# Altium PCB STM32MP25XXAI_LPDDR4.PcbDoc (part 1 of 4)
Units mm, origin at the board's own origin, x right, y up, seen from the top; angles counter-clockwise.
Board outline 172 x 137 mm, 4 copper layers (Top Layer, Signal Layer 1, Signal Layer 2, Bottom Layer), stack 1.614 mm thick; 188 components, 144 nets, 1216 pads, 838 vias.
Unrouted connection lines stored in the file: 13.
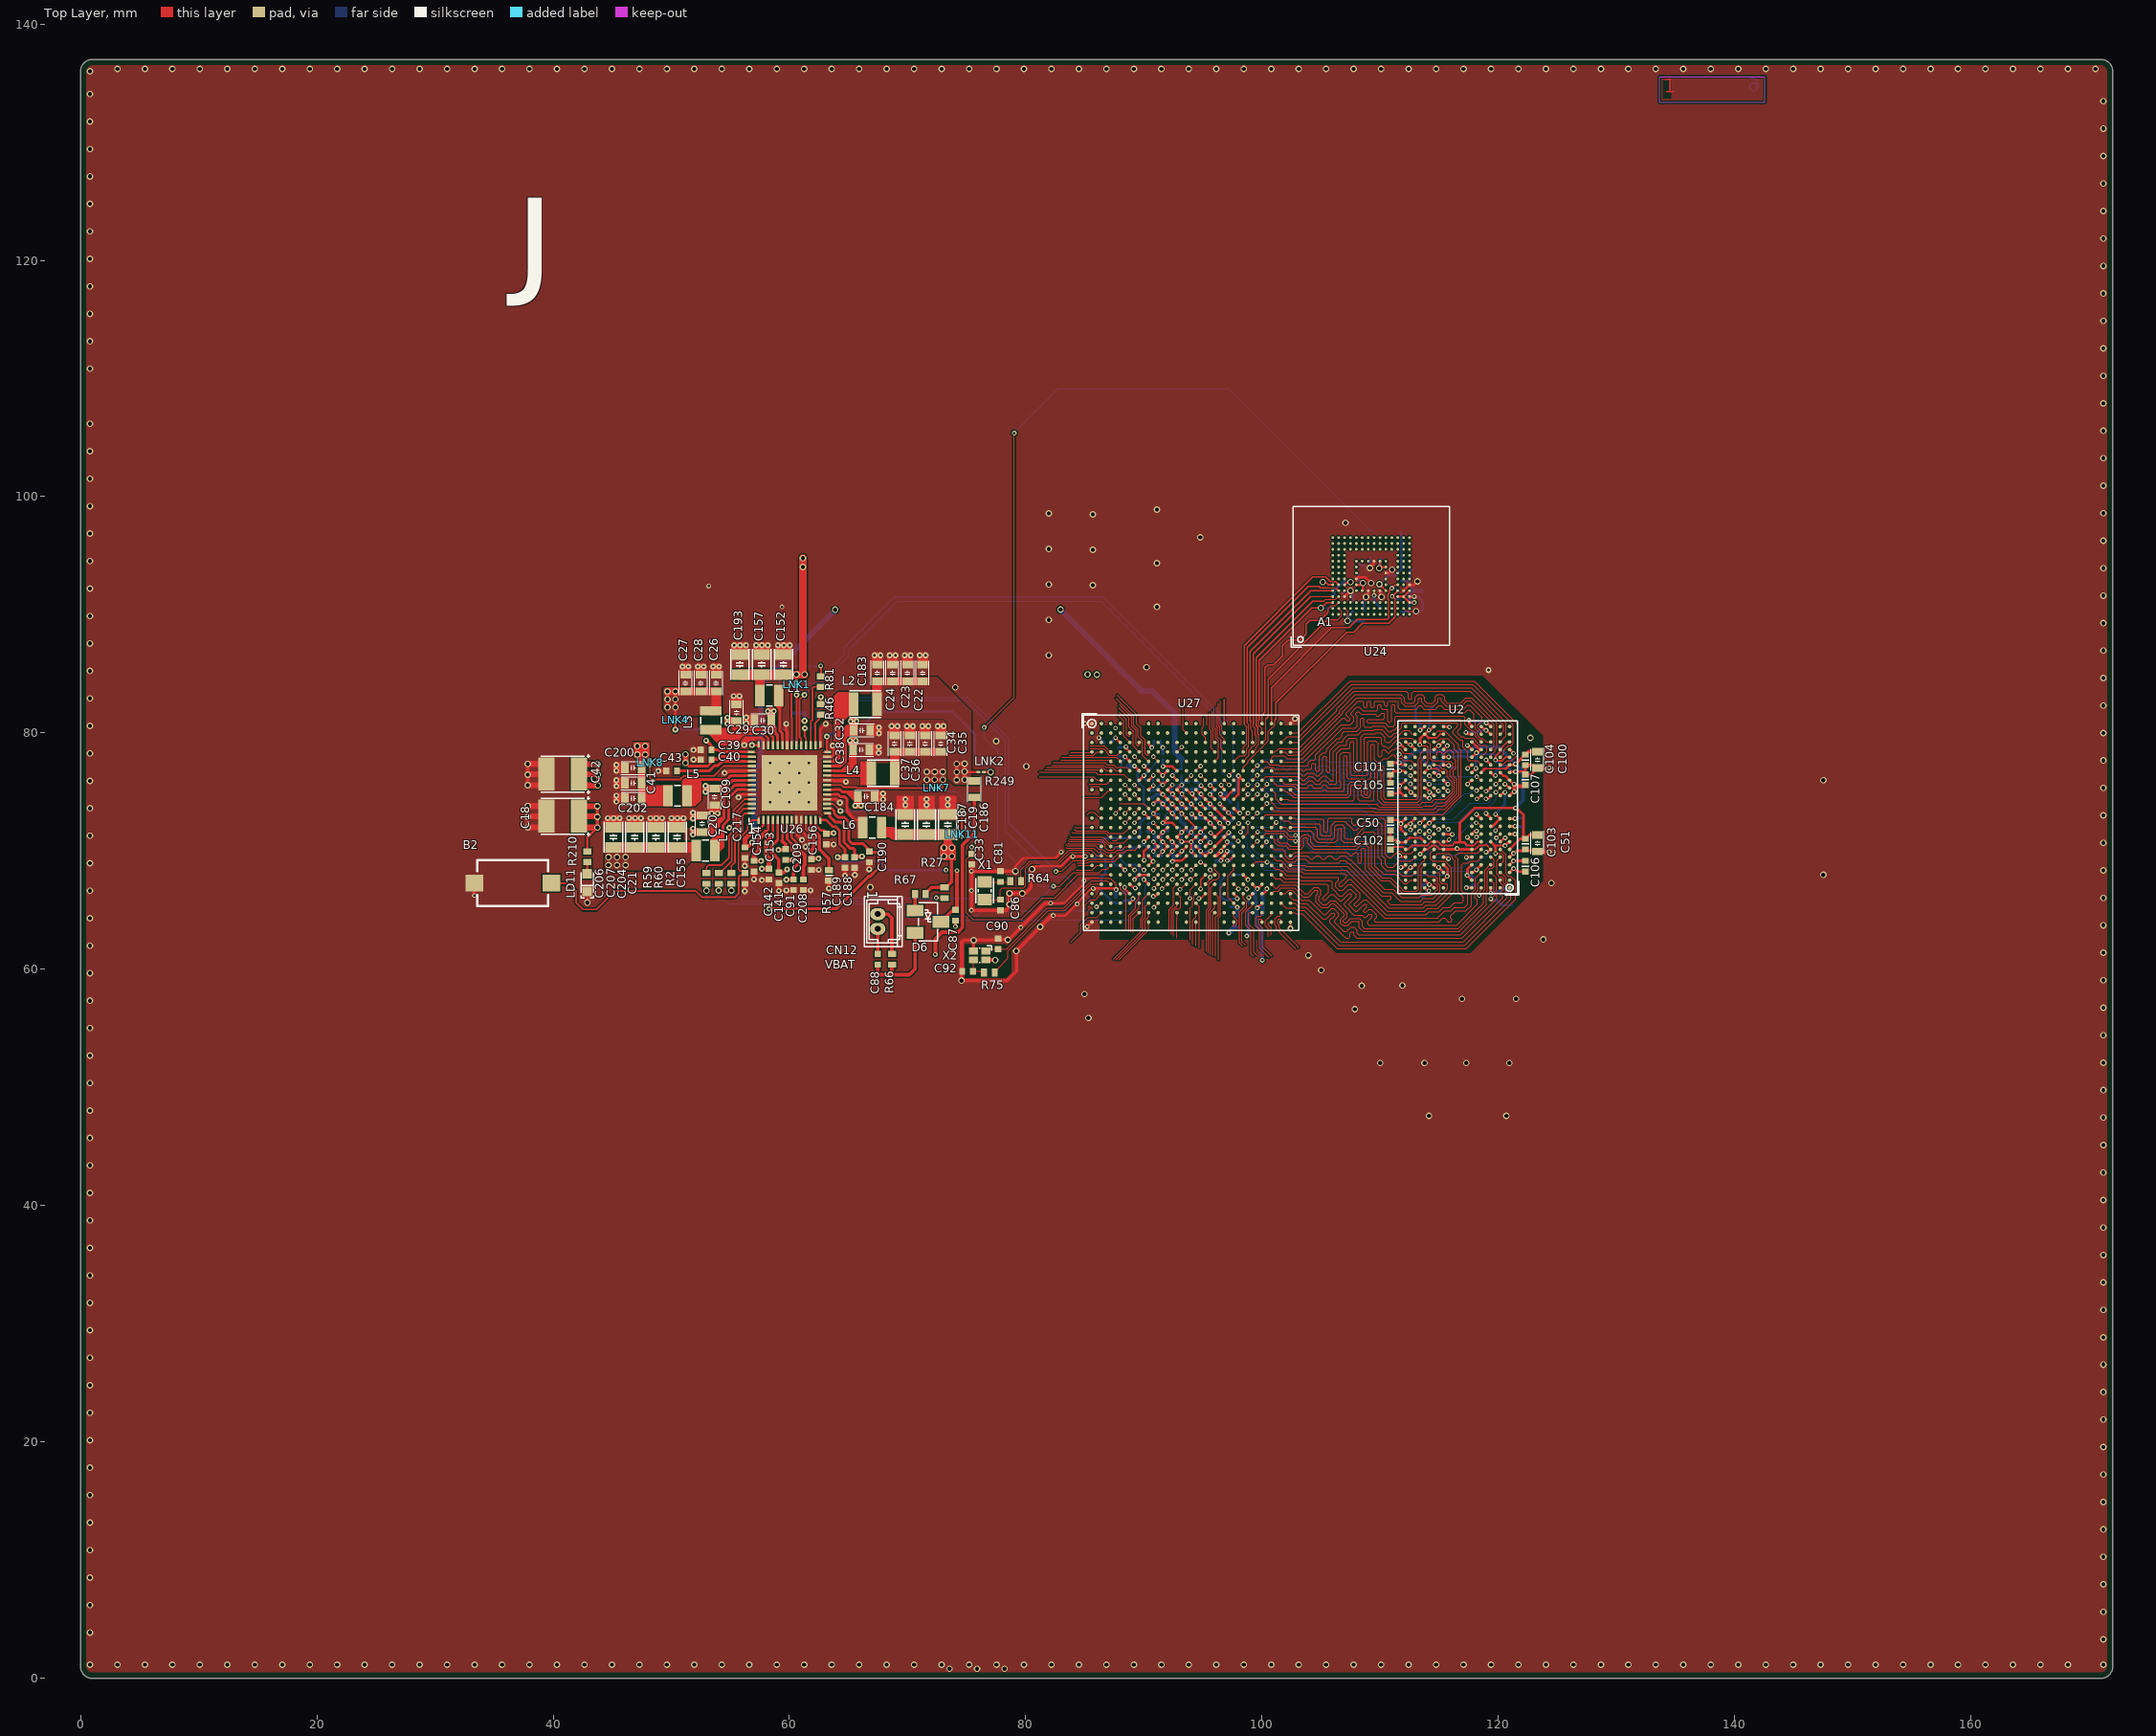
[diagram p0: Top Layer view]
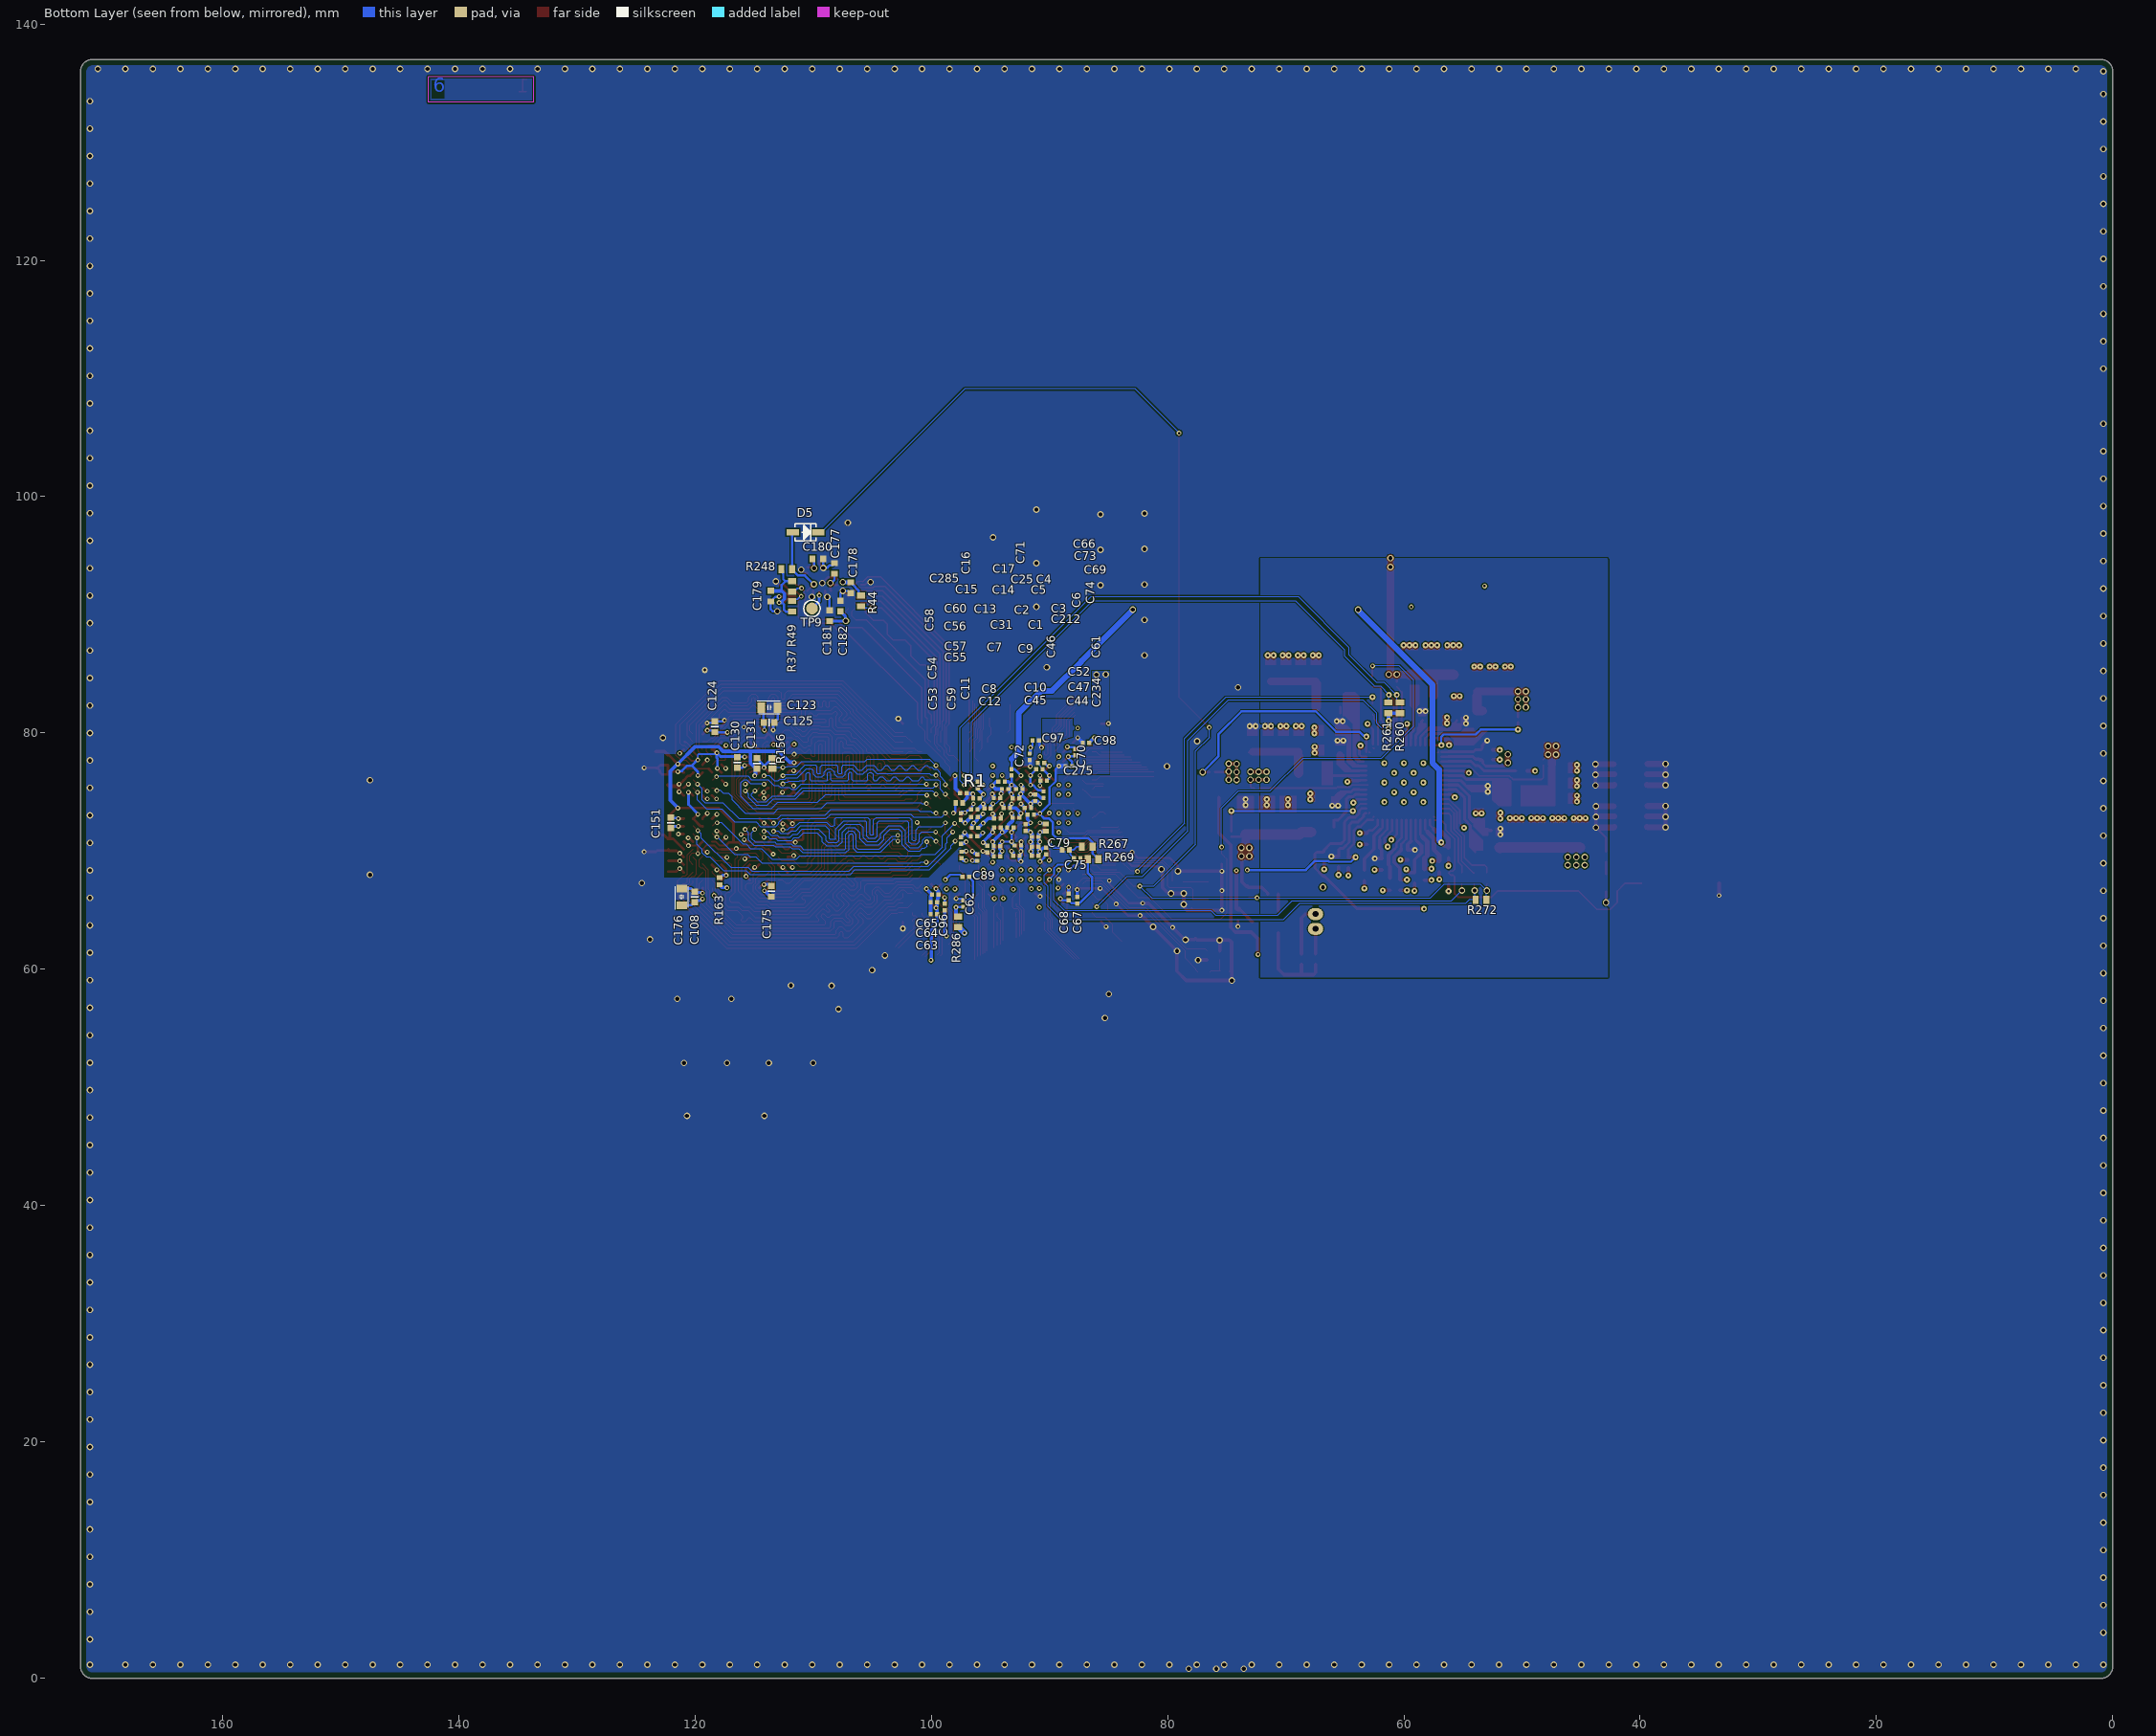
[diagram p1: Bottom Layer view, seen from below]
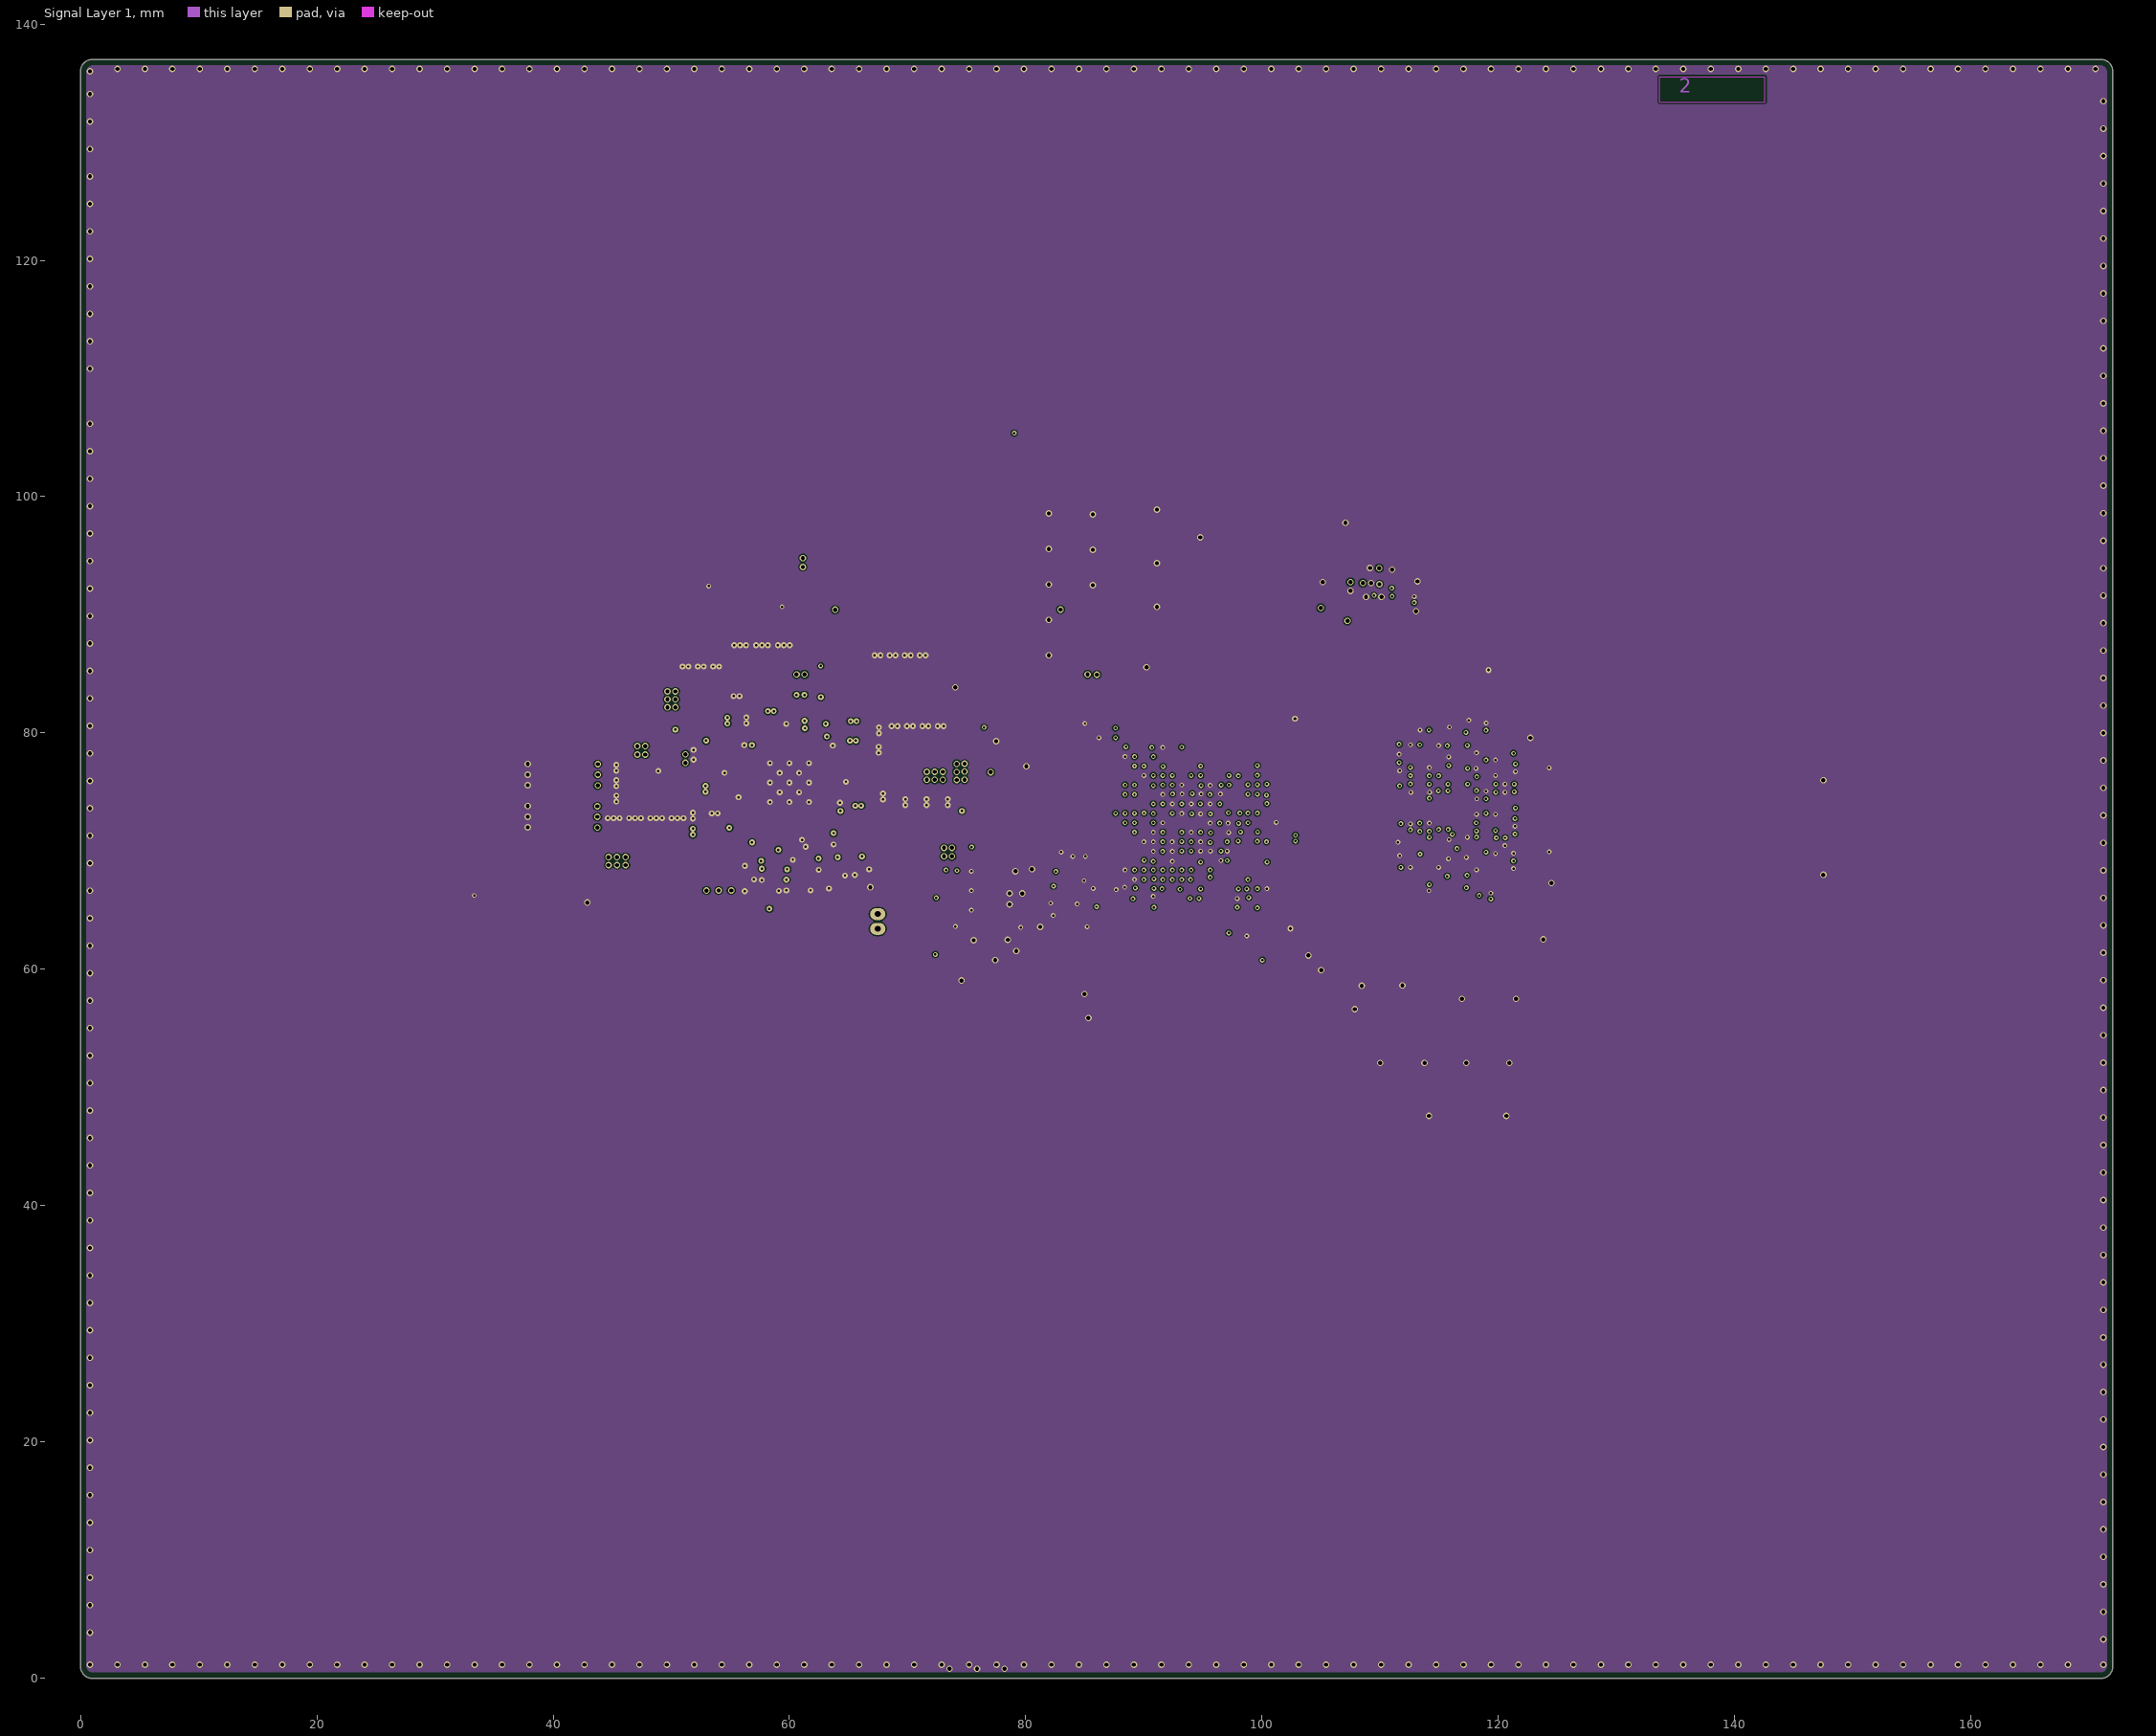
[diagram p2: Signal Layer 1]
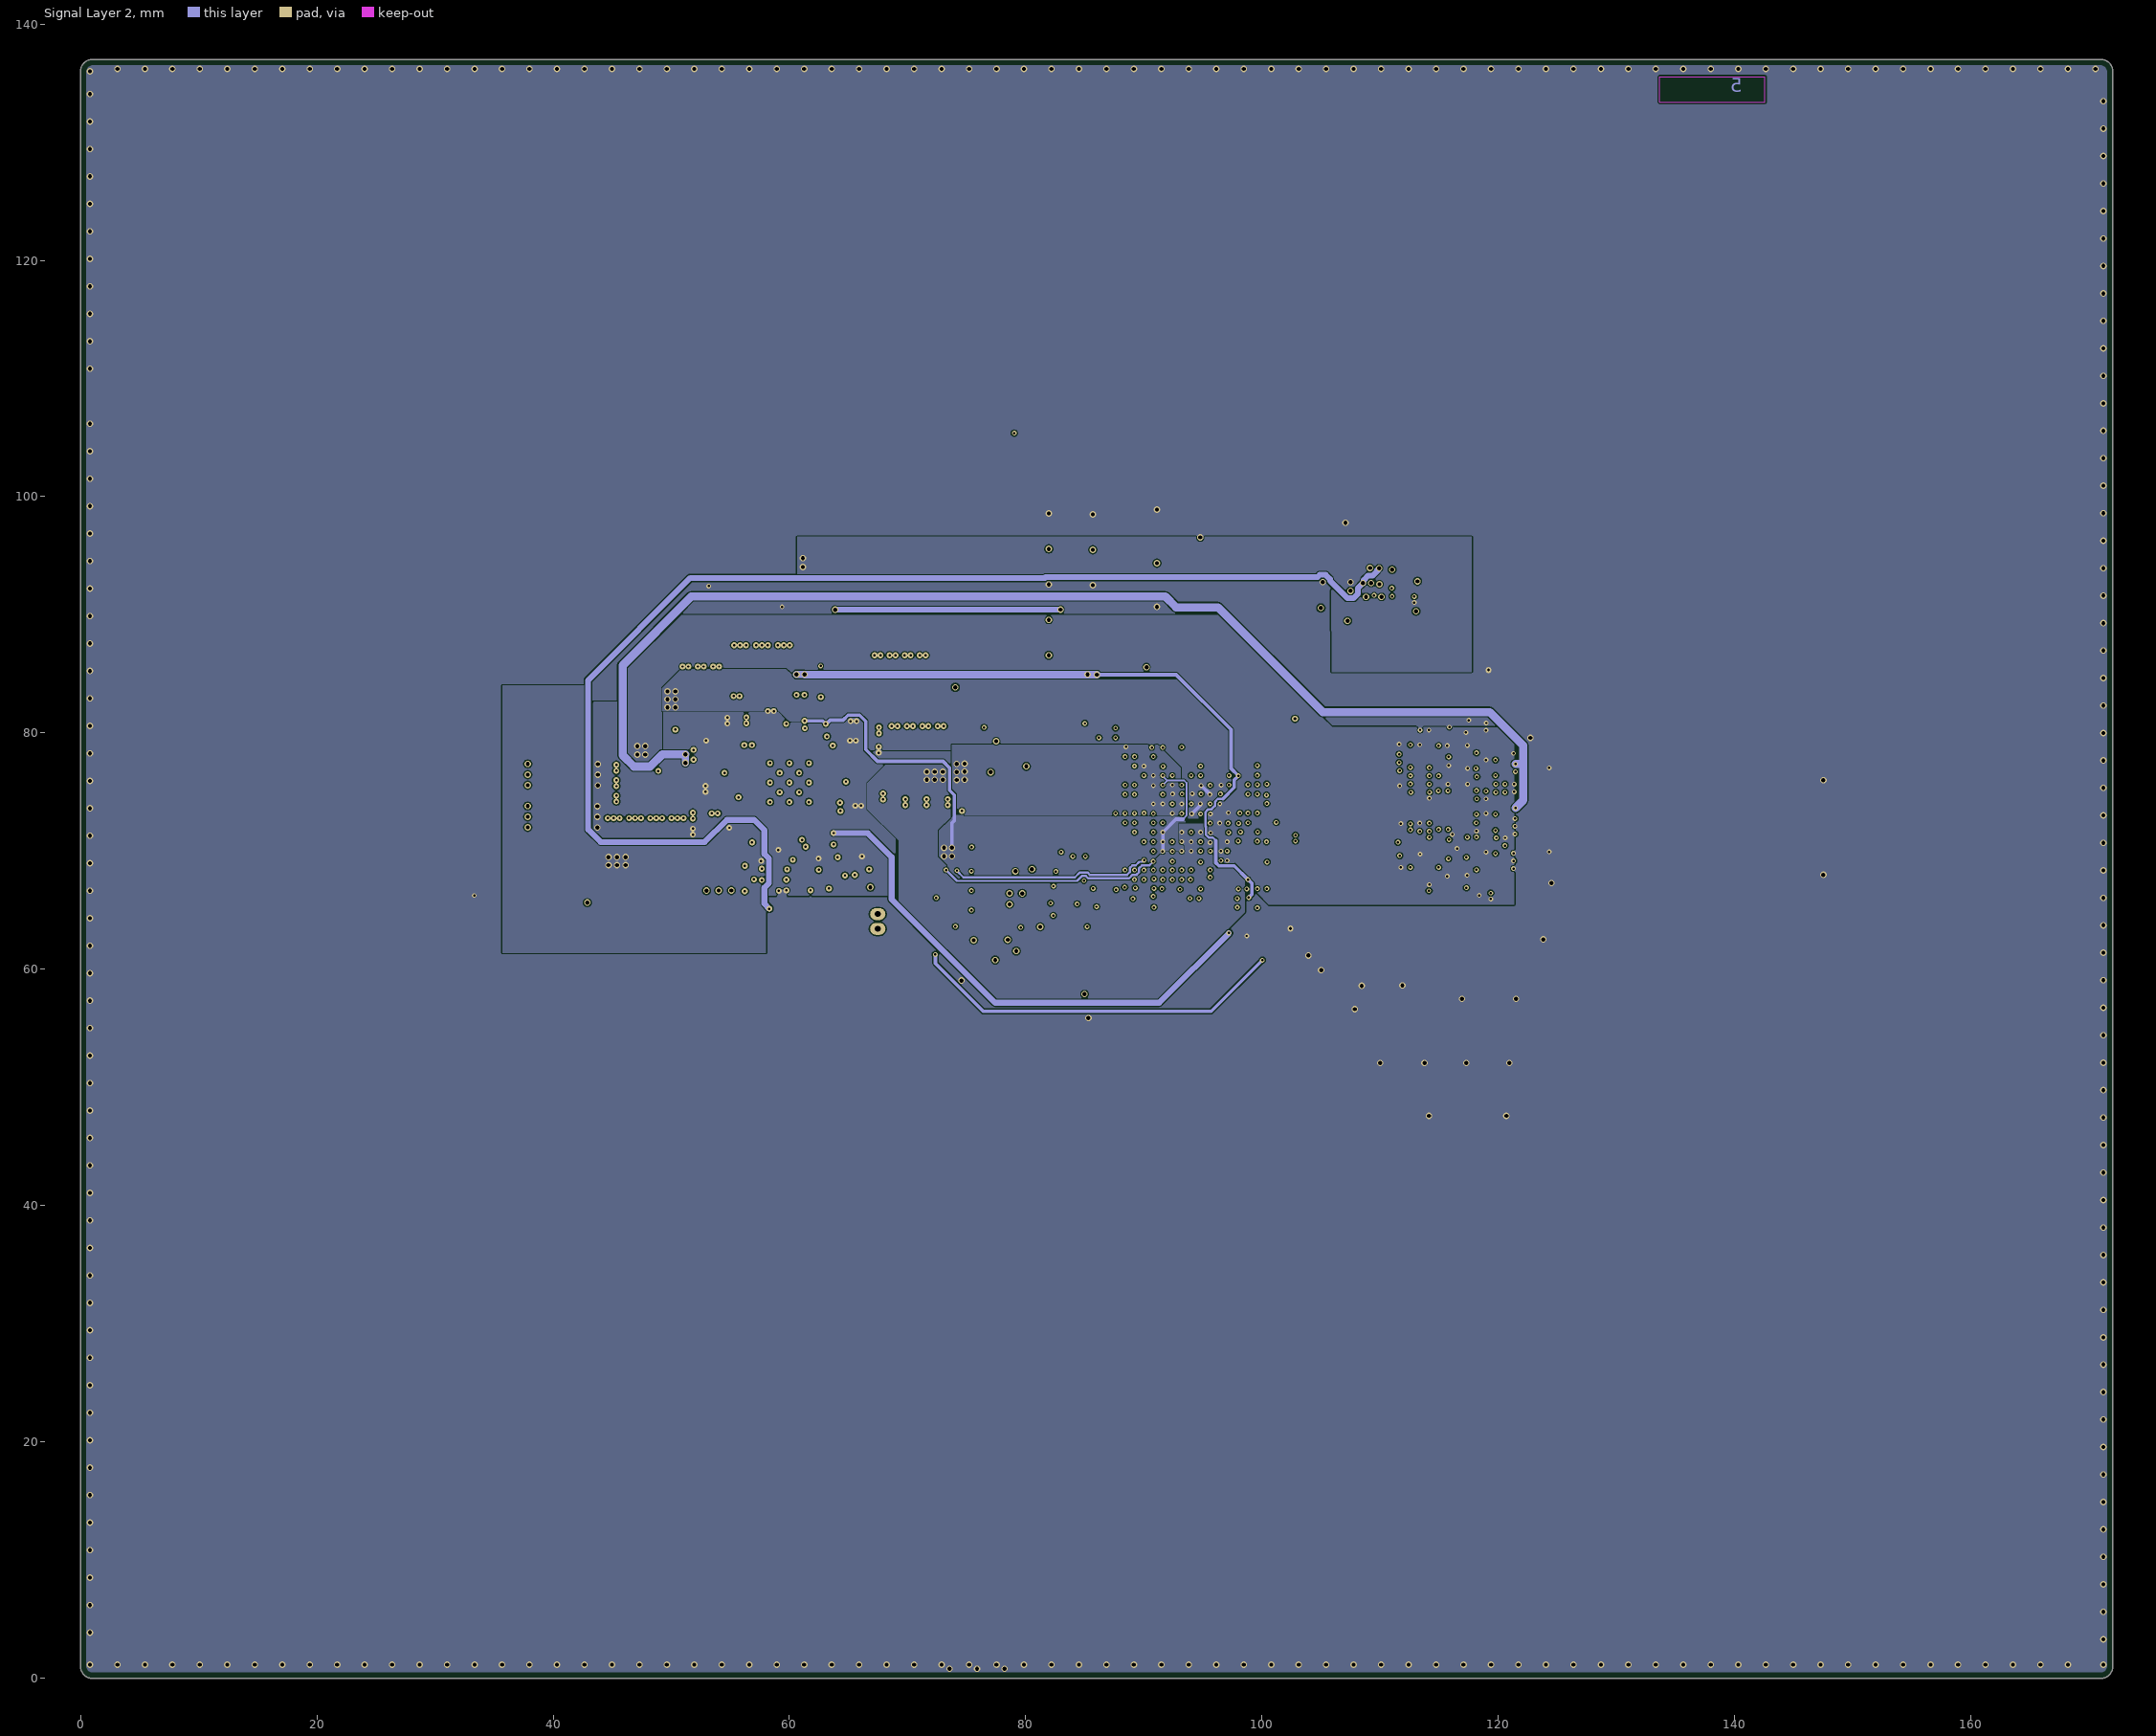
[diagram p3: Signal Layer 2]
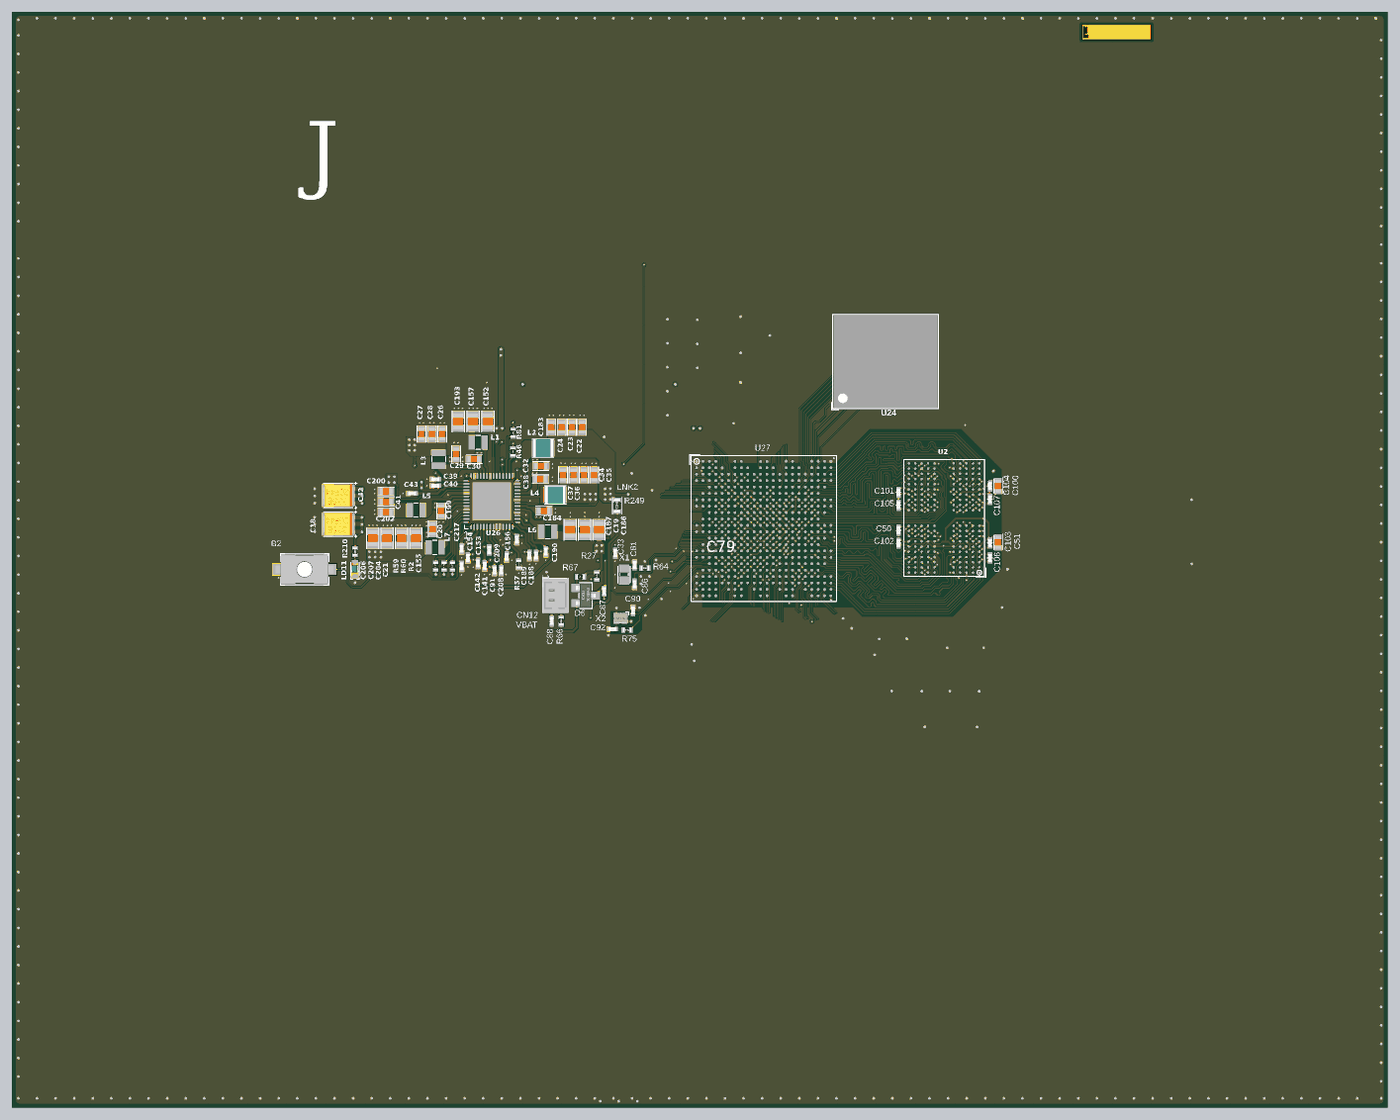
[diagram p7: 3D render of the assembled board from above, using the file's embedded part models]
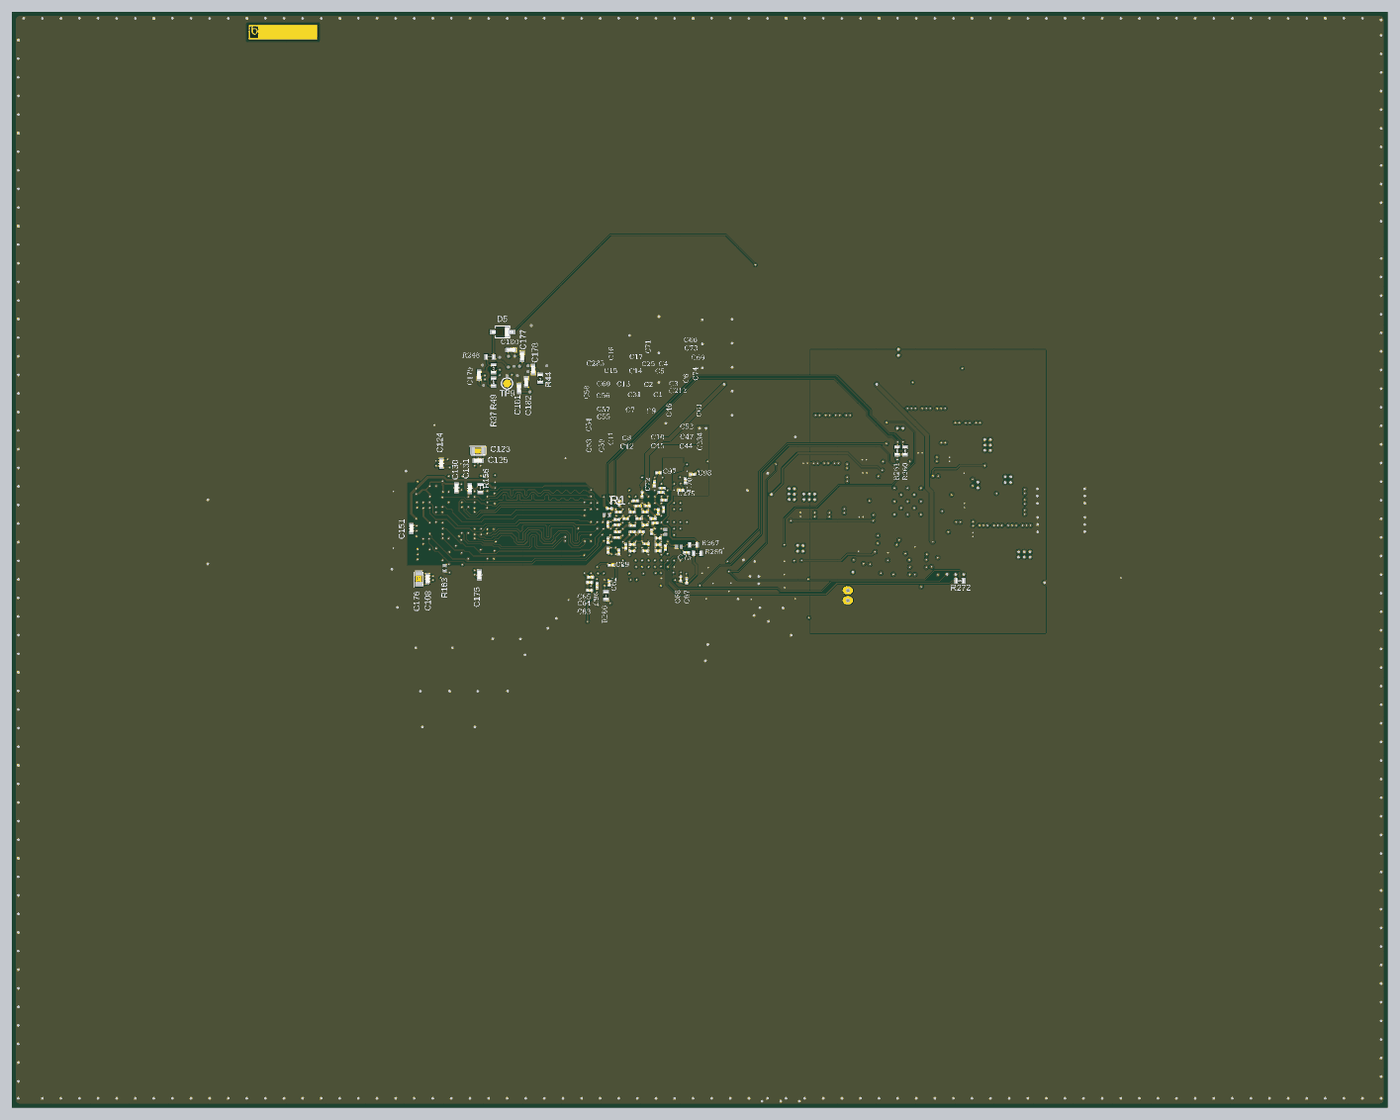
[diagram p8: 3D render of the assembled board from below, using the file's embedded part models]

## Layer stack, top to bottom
Top Solder: solder mask 0.025, Solder Resist, Dk 3.5
Top Layer: signal copper 0.037
Dielectric 1: prepreg 0.07, Dk 3.8
Signal Layer 1: signal copper 0.035
Dielectric 2: core 1.33, Dk 4.3
Signal Layer 2: signal copper 0.035
Dielectric 3: prepreg 0.07, Dk 3.8
Bottom Layer: signal copper 0.037
Bottom Solder: solder mask 0.025, Solder Resist, Dk 3.5

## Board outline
0,1 0,95 0,136 cw(c1,136) 1,137 171,137 cw(c171,136) 172,136 172,1 cw(c171,1) 171,0 1,0 cw(c1,1)

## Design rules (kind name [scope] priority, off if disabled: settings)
BoardOutlineClearance Silkscreen [OnLayer('Top Overlay') or OnLayer('Bottom Overlay')] p1: gap=0 ignorepadtopadclearanceinfootprint=FALSE
BoardOutlineClearance [All] p2: gap=0.5 ignorepadtopadclearanceinfootprint=FALSE
Clearance Clearance_Default [All] p1: gap=0.1 ignorepadtopadclearanceinfootprint=TRUE except(0: Arc-Hole Track-Hole SMDPad-Hole THPad-Hole Via-Hole Fill-Hole Poly-Hole Region-Hole Text-Hole; 0.09: Track-Track Track-SMDPad)
ComponentClearance [All] p1 off: gap=0.2 collisioncheckmode=3 verticalgap=0 showdistances=FALSE
DiffPairsRouting DiffPairsRouting_DDR_100R [InDifferentialPairClass('DPC_DDR_100R')] p1: maxlimit=0.16 minlimit=0.14 mostfreqgap=0.254 toplayer_mingap=0.16 toplayer_prefgap=0.16 toplayer_minwidth=0.09 toplayer_maxwidth=0.09 toplayer_prefwidth=0.09 bottomlayer_mingap=0.16 bottomlayer_prefgap=0.16 bottomlayer_minwidth=0.09 bottomlayer_maxwidth=0.09 bottomlayer_prefwidth=0.09 impedanceprofiledriven=TRUE impedanceprofileid={5106416E-43F8-41F8-8BCA-F68B3FB1C141} impedanceprofilevalue=100.000000 maxuncoupledlength=12.7
FanoutControl Fanout_BGA [IsBGA] p1: bgadir=Out bgaviamode=Closest fanoutstyle=Auto fanoutdirection=Alternating viagrid=0.025 // Fanout_BGA (Default Rule)
FanoutControl Fanout_LCC [IsLCC] p2: bgadir=Out bgaviamode=Closest fanoutstyle=Auto fanoutdirection=Alternating viagrid=0.025 // Fanout_LCC (Default Rule)
FanoutControl Fanout_SOIC [IsSOIC] p3: bgadir=Out bgaviamode=Closest fanoutstyle=Auto fanoutdirection=Alternating viagrid=0.025 // Fanout_SOIC (Default Rule)
FanoutControl Fanout_Small [(CompPinCount < 5)] p4: bgadir=Out bgaviamode=Closest fanoutstyle=Auto fanoutdirection=OutThenIn viagrid=0.025 // Fanout_Small (Default Rule)
FanoutControl Fanout_Default [All] p5: bgadir=Out bgaviamode=Closest fanoutstyle=Auto fanoutdirection=Alternating viagrid=0.025 // Fanout_Default (Default Rule)
HoleSize [All] p1: absolutevalues=TRUE maxlimit=10 minlimit=0.025 maxpercent=80.000 minpercent=20.000
HoleToHoleClearance [All] p1: gap=0.25 allowstackedmicrovias=TRUE
Length Length__SINGLE_SDMMC2_50R [InNetClass('NC_SINGLE_SDMMC2_50R')] p1: maxlimit=50 minlimit=0
MinimumSolderMaskSliver [All] p1: minsoldermaskwidth=0.07
PlaneConnect [All] p1: planeconnectstyle=Direct reliefexpansion=0.508 reliefentries=4 reliefconductorwidth=0.21 reliefairgap=0.21
PolygonConnect PolygonConnect_Default [All] p1: connectstyle=Direct reliefconductorwidth=0.25 reliefentries=4 polygonreliefangle="90 Angle" airgapwidth=0.25
RoutingVias RoutingVias_Default [All] p1: holewidth=0.15 width=0.4 viastyle="Through Hole" minholewidth=0.15 minwidth=0.4 maxholewidth=0.35 maxwidth=0.6 viatemplateguid#1={BF886351-5902-4D8E-87A9-DD407FAE4AFA} viatemplateguid#2={A479BBDC-94B7-4D18-B59D-B7A18B767B5F} viatemplateguid#3={564DD7E2-F718-4BCE-8A99-5417C9FECCB6} viatemplateguid#4={BB8F4C89-420F-4EBC-9772-FD82009DE81A} viatemplateguid#5={3FF096CA-B7A5-4E0B-A50A-8B2CD18CCC19} viatemplatename#1=v50h25m30mx30 viatemplatename#2=v55h35m40mx40 viatemplatename#3=v40h20m0mx0 viatemplatename#4=v40h20m25mx25 viatemplatename#5=v50h25m0mx0
ShortCircuit ShortCircuit_Link200 [InPadClass('PC_LINK200')] p1: allowed=TRUE
SilkToSilkClearance [All] p1: silktosilkclearance=0.2
SilkToSolderMaskClearance [IsPad] p1: minsilkscreentomaskgap=0.015 clearancetoexposedcopper=TRUE
SolderMaskExpansion [All] p1: expansion=0.1 istentingtop=FALSE
ViasUnderSMD [InPadClass('PC_VIAS-IN-PAD_OK')] p1: allowed=TRUE
Width Width_Default [InNetClass('All Nets')] p1: maxlimit=10 minlimit=0.09 preferedwidth=0.1
16 further rules are at their usual default settings.

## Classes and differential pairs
net class eMMC.SDMMC2_D[0..7]: eMMC.SDMMC2_D0 eMMC.SDMMC2_D1 eMMC.SDMMC2_D2 eMMC.SDMMC2_D3 eMMC.SDMMC2_D4 eMMC.SDMMC2_D5 eMMC.SDMMC2_D6 eMMC.SDMMC2_D7
component class "U_STM32MP25XXAI Power": C1 C2 C3 C4 C5 C6 C7 C8 C9 C10 C11 C12 C13 C14 C15 C16 C17 C25 C31 C44 C45 C46 C47 C52 C53 C54 C55 C56 C57 C58 C59 C60 C61 C62 C63 C64 C65 C66 C67 C68 C69 C70 C71 C72 C73 C74 C75 C79 C87 C88 C89 C96 C97 C98 C212 C234 C275 C285 CN12 D6 R66 R67 R249 R267 R269 R286
component class "U_STM32MP25XXAI I_Os": C33 C81 C86 C90 C92 R27 R64 R75 R260 R261 R272 U27 X1 X2
component class U_PMIC: B2 C18 C19 C20 C21 C22 C23 C24 C26 C27 C28 C29 C30 C32 C34 C35 C36 C37 C38 C39 C40 C41 C42 C43 C91 C141 C142 C152 C153 C154 C155 C156 C157 C183 C184 C186 C187 C188 C189 C190 C193 C199 C200 C202 C204 C206 C207 C208 C209 C217 L1 L2 L3 L4 L5 L6 L7 LD11 LNK1 LNK2 LNK4 LNK7 LNK8 LNK11 R2 R46 R57 R59 R60 R81 R210 U26
component class U_eMMC: C177 C178 C179 C180 C181 C182 D5 R37 R44 R49 R248 TP9 U24
component class U_2_LPDDR4_32bits: C50 C51 C100 C101 C102 C103 C104 C105 C106 C107 C108 C123 C124 C125 C130 C131 C151 C175 C176 R1 R156 R163 U2
differential pair DDR_DQS1_B: +DDR_DQS1_B_P -DDR_DQS1_B_N
differential pair DDR_DQS1_A: +DDR_DQS1_A_P -DDR_DQS1_A_N
differential pair DDR_DQS0_B: +DDR_DQS0_B_P -DDR_DQS0_B_N
differential pair DDR_DQS0_A: +DDR_DQS0_A_P -DDR_DQS0_A_N
differential pair DDR_CLK_B: +DDR_CLK_B_P -DDR_CLK_B_N
differential pair DDR_CLK_A: +DDR_CLK_A_P -DDR_CLK_A_N

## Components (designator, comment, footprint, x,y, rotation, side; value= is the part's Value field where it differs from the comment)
B2 "SW_PUSH_SMD_2P" SWI_WE_434121025816 36.59,67.295 r0 top value=434121025816
C1 "Capacitor" C0201_MURATA_GRM033_H0P3 92.825,72.825 r0 bottom value=1uF
C2 "Capacitor" C0201_MURATA_GRM033_H0P3 93.601,73.65 r180 bottom value=1uF
C3 "Capacitor" C0201_MURATA_GRM033_H0P3 91.825,73.65 r180 bottom value=1uF
C4 "Capacitor" C0201_MURATA_GRM033_H0P3 92.55,75.25 r0 bottom value=1uF
C5 "Capacitor" C0201_MURATA_GRM033_H0P3 92.826,74.475 r180 bottom value=1uF
C6 "Capacitor" C0201_MURATA_GRM033_H0P3 91.2,74.525 r270 bottom value=1uF
C7 "Capacitor" C0201_MURATA_GRM033_H0P3 94.4,72 r0 bottom value=1uF
C8 "Capacitor" C0201_MURATA_GRM033_H0P3 94.425,70.425 r180 bottom value=1uF
C9 "Capacitor" C0201_MURATA_GRM033_H0P3 93.3,72 r180 bottom value=1uF
C10 "Capacitor" C0201_MURATA_GRM033_H0P3 92.675,70.48 r0 bottom value=1uF
C11 "Capacitor" C0201_MURATA_GRM033_H0P3 95.25,70.175 r270 bottom value=1uF
C12 "Capacitor" C0201_MURATA_GRM033_H0P3 94.425,69.575 r180 bottom value=1uF
C13 "Capacitor" C0201_MURATA_GRM033_H0P3 95.232,73.625 r0 bottom value=1uF
C14 "Capacitor" C0201_MURATA_GRM033_H0P3 94.425,74.48 r180 bottom value=1uF
C15 "Capacitor" C0201_MURATA_GRM033_H0P3 96.175,74.475 r180 bottom value=1uF
C16 "Capacitor" C0201_MURATA_GRM033_H0P3 96.075,75.6 r90 bottom value=1uF
C17 "Capacitor" C0201_MURATA_GRM033_H0P3 94.05,75.875 r0 bottom value=1uF
C18 "Cap_POL_TANA" CPOL_TCJ-B_1210_H210 40.812,72.961 r180 top value=100uF
C19 "Capacitor" C0805 71.6,72.25 r270 top value=22uF
C20 "Capacitor" C0603 52.6,72.325 r270 top value=10uF
C21 "Capacitor" C0805 50.5,71.173 r270 top value=22uF
C22 "Capacitor" C0603 71.275,85.075 r270 top value=22uF
C23 "Capacitor" C0603 70,85.075 r270 top value=22uF
C24 "Capacitor" C0603 68.725,85.075 r270 top value=22uF
C25 "Capacitor" C0201_MURATA_GRM033_H0P3 93.75,75.25 r0 bottom value=1uF
C26 "Capacitor" C0603 53.8,84.225 r270 top value=22uF
C27 "Capacitor" C0603 51.2,84.225 r270 top value=22uF
C28 "Capacitor" C0603 52.5,84.225 r270 top value=22uF
C29 "Capacitor" C0603 55.525,81.725 r270 top value=10uF
C30 "Capacitor" C0603 57.75,81.075 r0 top value=10uF
C31 "Capacitor" C0201_MURATA_GRM033_H0P3 94.4,72.775 r180 bottom value=1uF
C32 "Capacitor" C0603 66.125,80.225 r180 top value=10uF
C33 "Capacitor" C0402 75.425,69.325 r90 top value=10nF
C34 "Capacitor" C0603 71.5,79.1 r270 top value=22uF
C35 "Capacitor" C0603 72.8,79.1 r270 top value=22uF
C36 "Capacitor" C0603 70.2,79.1 r270 top value=22uF
C37 "Capacitor" C0603 68.9,79.1 r270 top value=22uF
C38 "Capacitor" C0603 66.075,78.575 r180 top value=10uF
C39 "Capacitor" C0402 52.945,78.575 r0 top value=1uF
C40 "Capacitor" C0402 52.945,77.75 r0 top value=10uF
C41 "Capacitor" C0603 46.775,75.75 r0 top value=22uF
C42 "Cap_POL_TANA" CPOL_TCJ-B_1210_H210 40.812,76.523 r180 top value=100uF
C43 "Capacitor" C0402 50.035,76.8 r0 top value=1uF
C44 "Capacitor" C0201_MURATA_GRM033_H0P3 91.2,69.6 r180 bottom value=1uF
C45 "Capacitor" C0201_MURATA_GRM033_H0P3 92.8,69.6 r0 bottom value=1uF
C46 "Capacitor" C0201_MURATA_GRM033_H0P3 92.025,72 r270 bottom value=1uF
C47 "Capacitor" C0201_MURATA_GRM033_H0P3 91.2,70.388 r180 bottom value=1uF
C50 "Capacitor" C0402 110.85,72.2 r270 top value=100nF
C51 "Capacitor" C0603 123.3,70.675 r90 top value=10uF
C52 "Capacitor" C0201_MURATA_GRM033_H0P3 91.2,71.2 r0 bottom value=1uF
C53 "Capacitor" C0201_MURATA_GRM033_H0P3 97.45,69.675 r270 bottom value=1uF
C54 "Capacitor" C0201_MURATA_GRM033_H0P3 97.475,70.9 r90 bottom value=1uF
C55 "Capacitor" C0201_MURATA_GRM033_H0P3 96.375,71.275 r180 bottom value=1uF
C56 "Capacitor" C0201_MURATA_GRM033_H0P3 96.349,72.875 r180 bottom value=1uF
C57 "Capacitor" C0201_MURATA_GRM033_H0P3 96.301,71.974 r0 bottom value=1uF
C58 "Capacitor" C0201_MURATA_GRM033_H0P3 97.5,72.925 r90 bottom value=1uF
C59 "Capacitor" C0201_MURATA_GRM033_H0P3 96.1,69.45 r90 bottom value=1uF
C60 "Capacitor" C0201_MURATA_GRM033_H0P3 96.356,73.524 r0 bottom value=1uF
C61 "Capacitor" C0201_H0P5 90.317,71.988 r90 bottom value=4.7uF
C62 "Capacitor" C0201_MURATA_GRM033_H0P3 97.3,65.575 r270 bottom value=100nF
C63 "Capacitor" C0201_MURATA_GRM033_H0P3 99.775,64.675 r180 bottom value=100nF
C64 "Capacitor" C0201_MURATA_GRM033_H0P3 99.775,65.675 r180 bottom value=100nF
C65 "Capacitor" C0201_MURATA_GRM033_H0P3 99.65,66.325 r180 bottom value=100nF
C66 "Capacitor" C0201_MURATA_GRM033_H0P3 90.7,77.475 r180 bottom value=100nF
C67 "Capacitor" C0201_MURATA_GRM033_H0P3 87.63,65.845 r270 bottom value=1uF
C68 "Capacitor" C0201_MURATA_GRM033_H0P3 88.375,66.125 r270 bottom value=100nF
C69 "Capacitor" C0201_MURATA_GRM033_H0P3 90.48,75.97 r0 bottom value=100nF
C70 "Capacitor" C0201_MURATA_GRM033_H0P3 87.8,78.375 r90 bottom value=100nF
C71 "Capacitor" C0201_MURATA_GRM033_H0P3 93.201,76.675 r90 bottom value=100nF
C72 "Capacitor" C0201_MURATA_GRM033_H0P3 91.675,77.975 r270 bottom value=100nF
C73 "Capacitor" C0201_MURATA_GRM033_H0P3 90.85,76.925 r0 bottom value=100nF
C74 "Capacitor" C0201_MURATA_GRM033_H0P3 90.5,74.775 r90 bottom value=100nF
C75 "Capacitor" C0201_MURATA_GRM033_H0P3 87.65,69.425 r0 bottom value=100nF
C79 "Capacitor" C0201_H0P5 88.6,70.125 r180 bottom value=2.2uF
C81 "Capacitor" C0402 77.85,67.85 r90 top value=6.8pF
C86 "Capacitor" C0402 77.85,65.45 r270 top value=6.8pF
C87 "" C0402 74.05,64.575 r90 top value=100nF
C88 "Capacitor" C0402 67.475,60.85 r270 top value=2.2uF
C89 "Capacitor" C0201_MURATA_GRM033_H0P3 97.075,67.825 r0 bottom value=100nF
C90 "Capacitor" C0402 77.65,62.15 r270 top value=6.8pF
C91 "Capacitor" C0402 60.345,67.16 r270 top value=4.7uF
C92 "Capacitor" C0402 75.075,59.825 r180 top value=6.8pF
C96 "Capacitor" C0201_MURATA_GRM033_H0P3 98.85,65.275 r90 bottom value=100nF
C97 "Capacitor" C0201_MURATA_GRM033_H0P3 91.15,79.375 r180 bottom value=100nF
C98 "Capacitor" C0201_MURATA_GRM033_H0P3 86.9,79.175 r0 bottom value=100nF
C100 "Capacitor" C0603 123.3,77.725 r90 top value=10uF
C101 "Capacitor" C0402 110.85,76.925 r90 top value=100nF
C102 "Capacitor" C0402 110.85,70.575 r270 top value=100nF
C103 "Capacitor" C0402 122.275,70.6 r90 top value=100nF
C104 "Capacitor" C0402 122.275,77.725 r90 top value=100nF
C105 "Capacitor" C0402 110.85,75.325 r270 top value=100nF
C106 "Capacitor" C0402 122.275,68.725 r270 top value=100nF
C107 "Capacitor" C0402 122.275,76.05 r90 top value=100nF
C108 "Capacitor" C0402 120.025,66.125 r90 bottom value=100nF
C123 "Capacitor" C0603 113.7,82.15 r0 bottom value=10uF
C124 "Capacitor" C0402 118.3,80.525 r90 bottom value=100nF
C125 "Capacitor" C0402 113.725,80.9 r180 bottom value=100nF
C130 "Capacitor" C0402 116.4,77.5 r90 bottom value=100nF
C131 "Capacitor" C0402 114.75,77.425 r270 bottom value=100nF
C141 "Capacitor" C0402 59.1,67.75 r270 top value=4.7uF
C142 "Capacitor" C0402 58.275,68.06 r270 top value=4.7uF
C151 "Capacitor" C0402 122.05,72.4 r270 bottom value=100nF
C152 "Capacitor" C0805 59.5,85.8 r270 top value=22uF
C153 "Capacitor" C0402 59.675,69.72 r90 top value=1uF
C154 "Capacitor" C0402 57,68.725 r90 top value=1uF
C155 "Capacitor" C0402 56.227,67.695 r90 top value=10nF
C156 "Capacitor" C0402 63.125,71.02 r90 top value=4.7uF
C157 "Capacitor" C0805 57.65,85.8 r270 top value=22uF
C175 "Capacitor" C0402 113.55,66.6 r270 bottom value=100nF
C176 "Capacitor" C0603 121.125,66.125 r270 bottom value=10uF
C177 "Capacitor" C0402 108.2,93.925 r270 bottom value=100nF
C178 "Capacitor" C0402 106.825,92.3 r90 bottom value=2.2uF
C179 "Capacitor" C0402 113.59,91.58 r90 bottom value=100nF
C180 "Capacitor" C0402 109.6,94.739 r0 bottom value=2.2uF
C181 "Capacitor" C0402 108.6,89.925 r270 bottom value=2.2uF
C182 "Capacitor" C0402 107.685,90.75 r270 bottom value=100nF
C183 "Capacitor" C0603 67.45,85.075 r270 top value=22uF
C184 "Capacitor" C0603 66.497,74.625 r180 top value=10uF
C186 "Capacitor" C0805 73.4,72.25 r270 top value=22uF
C187 "Capacitor" C0805 69.8,72.25 r270 top value=22uF
C188 "Capacitor" C0402 65.525,69.04 r90 top value=1uF
C189 "Capacitor" C0402 64.7,69.04 r90 top value=4.7uF
C190 "Capacitor" C0402 66.75,69.515 r270 top value=4.7uF
C193 "Capacitor" C0805 55.8,85.8 r270 top value=22uF
C199 "Capacitor" C0603 53.675,74.6 r90 top value=10uF
C200 "Capacitor" C0603 46.775,77.05 r0 top value=22uF
C202 "Capacitor" C0603 46.775,74.45 r0 top value=22uF
C204 "Capacitor" C0805 48.7,71.173 r270 top value=22uF
C206 "Capacitor" C0805 45.1,71.173 r270 top value=22uF
C207 "Capacitor" C0805 46.9,71.173 r270 top value=22uF
C208 "Capacitor" C0402 61.17,67.16 r270 top value=4.7uF
C209 "Capacitor" C0402 61.85,68.87 r90 top value=4.7uF
C212 "Capacitor" C0201_MURATA_GRM033_H0P3 91.585,73.1 r180 bottom value=100nF
C217 "Capacitor" C0402 56.225,69.87 r270 top value=4.7uF
C234 "Capacitor" C0201_MURATA_GRM033_H0P3 90.275,70.01 r270 bottom value=100nF
C275 "Capacitor" C0201_MURATA_GRM033_H0P3 88.35,77.2 r0 bottom value=100nF
C285 "Capacitor" C0201_MURATA_GRM033_H0P3 97.28,74.91 r0 bottom value=100nF
CN12 "" CON_MOLEX_53047-0210 67.475,64.05 r270 top value="Header 2x1"
D5 "BAT60JFILM" DIO_SOD323 110.65,96.975 r180 bottom
D6 "DIODE_3P_DUAL_COMMON_CATHODE" DIO_SOT23 71.725,64.025 r270 top value=BAT54CFILM
L1 "Inductor" IND_2016_MURATA_LQM2MPN2R2NG0 58.295,83.175 r180 top value=2.2uH
L2 "Inductor" IND_2520_TOKO_DFE252012P 66.415,82.45 r0 top value=0.68µH
L3 "Inductor" IND_2016_MURATA_LQM2MPN2R2NG0 53.35,81.075 r90 top value=0.68uH
L4 "Inductor" IND_2520_TOKO_DFE252012P 67.925,76.6 r0 top value=0.68µH
L5 "Inductor" IND_2016_MURATA_LQM2MPN2R2NG0 50.525,74.7 r180 top value=0.68uH
L6 "Inductor" IND_2016_MURATA_LQM2MPN2R2NG0 67,72 r0 top value=2.2uH
L7 "Inductor" IND_2016_MURATA_LQM2MPN2R2NG0 52.9,70.05 r180 top value=0.68uH
LD11 "LED_green" LED_0603_OSRAM_LG-Q396-PS-35_GREEN_1A2K_H0P4 42.887,67.327 r270 top value=GREEN
LNK1 "link_200" LINK200 60.6,84.123 r0 top
LNK2 "link_200" LINK200 76.219,76.687 r90 top
LNK4 "link_200" LINK200 50.35,81.125 r180 top
LNK7 "link_200" LINK200 72.45,75.35 r270 top
LNK8 "link_200" LINK200 48.2,77.498 r0 top
LNK11 "link_200" LINK200 74.6,71.44 r180 top
R1 "Resistor" R0201_H0P23 97.627,74.077 r0 bottom value=240R
R2 "" R0402 55.08,67.695 r90 top value=0R
R27 "Resistor" R0402 73.125,66.475 r90 top value=10K
R37 "Resistor" R0402 111.775,90.725 r270 bottom value=10K
R44 "Resistor" R0402 105.95,91.18 r90 bottom value=10K
R46 "" R0402 62.65,81.998 r270 top value=0R
R49 "Resistor" R0402 111.775,92.4 r90 bottom value=10K
R57 "" R0402 63.35,67.95 r90 top value=0R
R59 "" R0402 52.98,67.695 r90 top value=0R
R60 "" R0402 54.03,67.695 r90 top value=0R
R64 "" R0402 79.15,67.45 r180 top value=0R
R66 "Resistor" R0402 68.675,60.845 r270 top value=20R
R67 "Resistor" R0402 71.075,66.375 r0 top value=0R
R75 "" R0402 76.925,59.725 r0 top value=0R
R81 "" R0402 62.663,84.348 r270 top value=0R
R156 "Resistor" R0402 113.425,77.425 r270 bottom value=10K
R163 "Resistor" R0201_H0P23 117.9,67.45 r90 bottom value=240R
R210 "Resistor" R0402 42.887,69.52 r270 top value=270R
R248 "Resistor" R0402 112.232,93.855 r0 bottom value=10K
R249 "Resistor" R0603 75.65,75.25 r270 top value=0R
R260 "Resistor" R0402 60.33,82.13 r270 bottom value=1K5
R261 "Resistor" R0402 61.305,82.13 r270 bottom value=1K5
R267 "" R0402 86.8,70.375 r180 bottom value=0R
R269 "" R0402 86.304,69.315 r0 bottom value=0R
R272 "Resistor" R0402 53.475,65.879 r0 bottom value=10K
R286 "" R0402 97.725,64.025 r90 bottom value=0R
TP9 "Test Point" TP_SMD_1MM 110.091,90.54 r90 bottom
U2 "MT53E1G32D2FW-046 WT:C" ICC_TFBGA200_10X14P5_P080_H1P05_PS0P3 116.55,73.725 r180 top
U24 "eMMC_THGBMTG5D1LBAIL" ICC_P-WFBGA153_13X11P5_P050 109.23,93.292 r0 top value=THGBMTG5D1LBAIL
U26 "STPMIC25APQR" ICC_QFN56-EPAD_6P5X6P5_P040 60,75.8 r90 top
U27 "STM32MP257FAI3" ICC_LFBGA436_18X18_P080_H1P70_STM32MP257_CODE-B0D1 94,72.4 r0 top locked
X1 "XTAL_2_PINS" CRY_NX2012SA_2P 76.525,66.65 r270 top value=32.768KHz
X2 "XTAL_4_PINS" CRY_NX1612SA_4P 76.098,61.176 r180 top value=40MHz

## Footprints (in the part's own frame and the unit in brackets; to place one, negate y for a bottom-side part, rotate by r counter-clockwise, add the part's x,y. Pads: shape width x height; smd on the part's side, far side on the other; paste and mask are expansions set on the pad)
C0201_H0P5 [mm] "MCD-01534"
  rect 0.4x0.5 smd mask+0.05: 1(-0.3,0) 2(0.3,0)
  body extent -0.35,-0.2 0.35,0.2, height 0.55
C0201_MURATA_GRM033_H0P3 [mm] "GRM033R60J105ME11"
  rect 0.35x0.35 smd mask+0.05: 1(-0.275,0) 2(0.275,0)
  body extent -0.32,-0.17 0.32,0.17, height 0.33
C0402 [mm]
  rect 0.51x0.56 smd mask+0.05: 1(-0.45,0) 2(0.45,0)
  body extent -0.5,-0.3 0.5,0.3, height 0.4
C0603 [mm]
  rect 0.64x0.89 smd mask+0.05: 1(-0.7,0) 2(0.7,0)
  silkscreen extent -1.05,-0.55 1.02,0.55, body extent -0.9,-0.5 0.9,0.5, height 1.4
C0805 [mm]
  rect 0.9x1.4 smd mask+0.05: 1(-0.85,0) 2(0.85,0)
  silkscreen extent -1.3,-0.77 1.3,0.77, body extent -1.1,-0.7 1.1,0.7, height 1.35
CON_MOLEX_53047-0210 [mm]
  oval 1x1.3 hole 0.5 mask+0.05: 1(-0.625,0) 2(0.625,0)
  silkscreen extent -2.12,-1.15 2.13,2.05, body extent -2.13,-1.15 2.13,2.05, height 4.2
CPOL_TCJ-B_1210_H210 [mm] "MCD-01791"
  rect 1.35x2.8 smd mask+0.05: 1(-1.375,0) 2(1.375,0)
  silkscreen extent -2.33,-1.68 1.85,1.68, body extent -1.85,-1.5 1.85,1.5, height 2.11
CRY_NX1612SA_4P [mm] "MCD-02262"
  rect 0.75x0.6 smd mask+0.038: 1(-0.525,-0.375) 2(0.525,-0.375) 3(0.525,0.375) 4(-0.525,0.375)
  silkscreen extent -1.02,-0.8 0.03,0.6, body extent -0.8,-0.6 0.8,0.6, height 0.51
CRY_NX2012SA_2P [mm]
  rect 1x1.25 smd mask+0.05: 1(-0.75,0) 2(0.75,0)
  silkscreen extent -1.05,-0.75 1.05,0.75, body extent -1.05,-0.63 1.05,0.63, height 0.6
DIO_SOD323 [mm]
  rect 1.06x0.54 smd mask+0.05: 1(-1.07,0) 2(1.07,0)
  silkscreen extent -0.9,-0.72 0.9,0.72, body extent -1.3,-0.78 1.3,0.78, height 1.17
DIO_SOT23 [mm]
  rect 1x1.4 smd mask+0.05: 1(-0.95,-1.1) 2(0.95,-1.1) 3(0,1.1)
  silkscreen extent -1.63,-0.82 1.63,0.82, body extent -1.56,-1.25 1.56,1.25, height 1.1
ICC_LFBGA436_18X18_P080_H1P70_STM32MP257_CODE-B0D1 [mm] "MCD02000"
  round 0.3 smd paste+0.025 mask+0.05: A1(-8.4,8.4) A2(-7.6,8.4) A3(-6.8,8.4) A4(-6,8.4) A7(-3.6,8.4) A8(-2.8,8.4) A11(-0.4,8.4) A12(0.4,8.4) A15(2.8,8.4) A16(3.6,8.4) A19(6,8.4) A20(6.8,8.4) A21(7.6,8.4) A22(8.4,8.4) AA1(-8.4,-7.6) AA2(-7.6,-7.6) AA3(-6.8,-7.6) AA4(-6,-7.6) AA6(-4.4,-7.6) AA7(-3.6,-7.6) AA8(-2.8,-7.6) AA10(-1.2,-7.6) AA11(-0.4,-7.6) AA12(0.4,-7.6) AA14(2,-7.6) AA15(2.8,-7.6) AA16(3.6,-7.6) AA18(5.2,-7.6) AA19(6,-7.6) AA20(6.8,-7.6) AA21(7.6,-7.6) AA22(8.4,-7.6) AB1(-8.4,-8.4) AB2(-7.6,-8.4) AB3(-6.8,-8.4) AB4(-6,-8.4) AB7(-3.6,-8.4) AB8(-2.8,-8.4) AB11(-0.4,-8.4) AB12(0.4,-8.4) AB15(2.8,-8.4) AB16(3.6,-8.4) AB19(6,-8.4) AB20(6.8,-8.4) AB21(7.6,-8.4) AB22(8.4,-8.4) B1(-8.4,7.6) B2(-7.6,7.6) B3(-6.8,7.6) B4(-6,7.6) B5(-5.2,7.6) B7(-3.6,7.6) B8(-2.8,7.6) B9(-2,7.6) B11(-0.4,7.6) B12(0.4,7.6) B13(1.2,7.6) B15(2.8,7.6) B16(3.6,7.6) B17(4.4,7.6) B19(6,7.6) B20(6.8,7.6) B21(7.6,7.6) B22(8.4,7.6) C1(-8.4,6.8) C2(-7.6,6.8) C3(-6.8,6.8) C4(-6,6.8) C5(-5.2,6.8) C6(-4.4,6.8) C7(-3.6,6.8) C8(-2.8,6.8) C9(-2,6.8) C10(-1.2,6.8) C11(-0.4,6.8) C12(0.4,6.8) C13(1.2,6.8) C14(2,6.8) C15(2.8,6.8) C16(3.6,6.8) C17(4.4,6.8) C18(5.2,6.8) C19(6,6.8) C20(6.8,6.8) C21(7.6,6.8) C22(8.4,6.8) D1(-8.4,6) D2(-7.6,6) D3(-6.8,6) D4(-6,6) D5(-5.2,6) D6(-4.4,6) D7(-3.6,6) D8(-2.8,6) D9(-2,6) D10(-1.2,6) D11(-0.4,6) D12(0.4,6) D13(1.2,6) D14(2,6) D15(2.8,6) D16(3.6,6) D17(4.4,6) D18(5.2,6) D19(6,6) D20(6.8,6) D21(7.6,6) D22(8.4,6) E3(-6.8,5.2) E4(-6,5.2) E5(-5.2,5.2) E6(-4.4,5.2) E7(-3.6,5.2) E8(-2.8,5.2) E9(-2,5.2) E10(-1.2,5.2) E11(-0.4,5.2) E12(0.4,5.2) E13(1.2,5.2) E14(2,5.2) E15(2.8,5.2) E16(3.6,5.2) E17(4.4,5.2) E18(5.2,5.2) E19(6,5.2) E20(6.8,5.2) E21(7.6,5.2) F2(-7.6,4.4) F3(-6.8,4.4) F4(-6,4.4) F5(-5.2,4.4) F6(-4.4,4.4) F7(-3.6,4.4) F8(-2.8,4.4) F9(-2,4.4) F10(-1.2,4.4) F11(-0.4,4.4) F12(0.4,4.4) F13(1.2,4.4) F14(2,4.4) F15(2.8,4.4) F16(3.6,4.4) F17(4.4,4.4) F18(5.2,4.4) F19(6,4.4) F20(6.8,4.4) G1(-8.4,3.6) G2(-7.6,3.6) G3(-6.8,3.6) G4(-6,3.6) G5(-5.2,3.6) G6(-4.4,3.6) G7(-3.6,3.6) G8(-2.8,3.6) G9(-2,3.6) G10(-1.2,3.6) G11(-0.4,3.6) G12(0.4,3.6) G13(1.2,3.6) G14(2,3.6) G15(2.8,3.6) G16(3.6,3.6) G17(4.4,3.6) G18(5.2,3.6) G19(6,3.6) G20(6.8,3.6) G21(7.6,3.6) G22(8.4,3.6) H1(-8.4,2.8) H2(-7.6,2.8) H3(-6.8,2.8) H4(-6,2.8) H5(-5.2,2.8) H6(-4.4,2.8) H7(-3.6,2.8) H8(-2.8,2.8) H9(-2,2.8) H10(-1.2,2.8) H11(-0.4,2.8) H12(0.4,2.8) H13(1.2,2.8) H14(2,2.8) H15(2.8,2.8) H16(3.6,2.8) H17(4.4,2.8) H18(5.2,2.8) H19(6,2.8) H20(6.8,2.8) H21(7.6,2.8) H22(8.4,2.8) J3(-6.8,2) J4(-6,2) J5(-5.2,2) J6(-4.4,2) J7(-3.6,2) J8(-2.8,2) J9(-2,2) J10(-1.2,2) J11(-0.4,2) J12(0.4,2) J13(1.2,2) J14(2,2) J15(2.8,2) J16(3.6,2) J17(4.4,2) J18(5.2,2) J19(6,2) J20(6.8,2) J21(7.6,2) K2(-7.6,1.2) K3(-6.8,1.2) K4(-6,1.2) K5(-5.2,1.2) K6(-4.4,1.2) K7(-3.6,1.2) K8(-2.8,1.2) K9(-2,1.2) K10(-1.2,1.2) K11(-0.4,1.2) K12(0.4,1.2) K13(1.2,1.2) K14(2,1.2) K15(2.8,1.2) K16(3.6,1.2) K17(4.4,1.2) K18(5.2,1.2) K19(6,1.2) K20(6.8,1.2) L1(-8.4,0.4) L2(-7.6,0.4) L3(-6.8,0.4) L4(-6,0.4) L5(-5.2,0.4) L6(-4.4,0.4) L7(-3.6,0.4) L8(-2.8,0.4) L9(-2,0.4) L10(-1.2,0.4) L11(-0.4,0.4) L12(0.4,0.4) L13(1.2,0.4) L14(2,0.4) L15(2.8,0.4) L16(3.6,0.4) L17(4.4,0.4) L18(5.2,0.4) L19(6,0.4) L20(6.8,0.4) L21(7.6,0.4) L22(8.4,0.4) M1(-8.4,-0.4) M2(-7.6,-0.4) M3(-6.8,-0.4) M4(-6,-0.4) M5(-5.2,-0.4) M6(-4.4,-0.4) M7(-3.6,-0.4) M8(-2.8,-0.4) M9(-2,-0.4) M10(-1.2,-0.4) M11(-0.4,-0.4) M12(0.4,-0.4) M13(1.2,-0.4) M14(2,-0.4) M15(2.8,-0.4) M16(3.6,-0.4) M17(4.4,-0.4) M18(5.2,-0.4) M19(6,-0.4) M20(6.8,-0.4) M21(7.6,-0.4) M22(8.4,-0.4) N3(-6.8,-1.2) N4(-6,-1.2) N5(-5.2,-1.2) N6(-4.4,-1.2) N7(-3.6,-1.2) N8(-2.8,-1.2) N9(-2,-1.2) N10(-1.2,-1.2) N11(-0.4,-1.2) N12(0.4,-1.2) N13(1.2,-1.2) N14(2,-1.2) N15(2.8,-1.2) N16(3.6,-1.2) N17(4.4,-1.2) N18(5.2,-1.2) N19(6,-1.2) N20(6.8,-1.2) N21(7.6,-1.2) P2(-7.6,-2) P3(-6.8,-2) P4(-6,-2) P5(-5.2,-2) P6(-4.4,-2) P7(-3.6,-2) P8(-2.8,-2) P9(-2,-2) P10(-1.2,-2) P11(-0.4,-2) P12(0.4,-2) P13(1.2,-2) P14(2,-2) P15(2.8,-2) P16(3.6,-2) P17(4.4,-2) P18(5.2,-2) P19(6,-2) P20(6.8,-2) R1(-8.4,-2.8) R2(-7.6,-2.8) R3(-6.8,-2.8) R4(-6,-2.8) R5(-5.2,-2.8) R6(-4.4,-2.8) R7(-3.6,-2.8) R8(-2.8,-2.8) R9(-2,-2.8) R10(-1.2,-2.8) R11(-0.4,-2.8) R12(0.4,-2.8) R13(1.2,-2.8) R14(2,-2.8) R15(2.8,-2.8) R16(3.6,-2.8) R17(4.4,-2.8) R18(5.2,-2.8) R19(6,-2.8) R20(6.8,-2.8) R21(7.6,-2.8) R22(8.4,-2.8) T1(-8.4,-3.6) T2(-7.6,-3.6) T3(-6.8,-3.6) T4(-6,-3.6) T5(-5.2,-3.6) T6(-4.4,-3.6) T7(-3.6,-3.6) T8(-2.8,-3.6) T9(-2,-3.6) T10(-1.2,-3.6) T11(-0.4,-3.6) T12(0.4,-3.6) T13(1.2,-3.6) T14(2,-3.6) T15(2.8,-3.6) T16(3.6,-3.6) T17(4.4,-3.6) T18(5.2,-3.6) T19(6,-3.6) T20(6.8,-3.6) T21(7.6,-3.6) T22(8.4,-3.6) U3(-6.8,-4.4) U4(-6,-4.4) U5(-5.2,-4.4) U6(-4.4,-4.4) U7(-3.6,-4.4) U8(-2.8,-4.4) U9(-2,-4.4) U10(-1.2,-4.4) U11(-0.4,-4.4) U12(0.4,-4.4) U13(1.2,-4.4) U14(2,-4.4) U15(2.8,-4.4) U16(3.6,-4.4) U17(4.4,-4.4) U18(5.2,-4.4) U19(6,-4.4) U20(6.8,-4.4) U21(7.6,-4.4) V2(-7.6,-5.2) V3(-6.8,-5.2) V4(-6,-5.2) V5(-5.2,-5.2) V6(-4.4,-5.2) V7(-3.6,-5.2) V8(-2.8,-5.2) V9(-2,-5.2) V10(-1.2,-5.2) V11(-0.4,-5.2) V12(0.4,-5.2) V13(1.2,-5.2) V14(2,-5.2) V15(2.8,-5.2) V16(3.6,-5.2) V17(4.4,-5.2) V18(5.2,-5.2) V19(6,-5.2) V20(6.8,-5.2) W1(-8.4,-6) W2(-7.6,-6) W3(-6.8,-6) W4(-6,-6) W5(-5.2,-6) W6(-4.4,-6) W7(-3.6,-6) W8(-2.8,-6) W9(-2,-6) W10(-1.2,-6) W11(-0.4,-6) W12(0.4,-6) W13(1.2,-6) W14(2,-6) W15(2.8,-6) W16(3.6,-6) W17(4.4,-6) W18(5.2,-6) W19(6,-6) W20(6.8,-6) W21(7.6,-6) W22(8.4,-6) Y1(-8.4,-6.8) Y2(-7.6,-6.8) Y3(-6.8,-6.8) Y4(-6,-6.8) Y5(-5.2,-6.8) Y6(-4.4,-6.8) Y7(-3.6,-6.8) Y8(-2.8,-6.8) Y9(-2,-6.8) Y10(-1.2,-6.8) Y11(-0.4,-6.8) Y12(0.4,-6.8) Y13(1.2,-6.8) Y14(2,-6.8) Y15(2.8,-6.8) Y16(3.6,-6.8) Y17(4.4,-6.8) Y18(5.2,-6.8) Y19(6,-6.8) Y20(6.8,-6.8) Y21(7.6,-6.8) Y22(8.4,-6.8)
  silkscreen extent -9.25,-9.1 9.1,9.25, body extent -9.1,-9.1 9.1,9.1, height 1.7
ICC_P-WFBGA153_13X11P5_P050 [mm]
  round 0.23 smd mask+0.05: A1(-3.25,-3.25) A2(-3.25,-2.75) A3(-3.25,-2.25) A4(-3.25,-1.75) A5(-3.25,-1.25) A6(-3.25,-0.75) A7(-3.25,-0.25) A8(-3.25,0.25) A9(-3.25,0.75) A10(-3.25,1.25) A11(-3.25,1.75) A12(-3.25,2.25) A13(-3.25,2.75) A14(-3.25,3.25) B1(-2.75,-3.25) B2(-2.75,-2.75) B3(-2.75,-2.25) B4(-2.75,-1.75) B5(-2.75,-1.25) B6(-2.75,-0.75) B7(-2.75,-0.25) B8(-2.75,0.25) B9(-2.75,0.75) B10(-2.75,1.25) B11(-2.75,1.75) B12(-2.75,2.25) B13(-2.75,2.75) B14(-2.75,3.25) C1(-2.25,-3.25) C2(-2.25,-2.75) C3(-2.25,-2.25) C4(-2.25,-1.75) C5(-2.25,-1.25) C6(-2.25,-0.75) C7(-2.25,-0.25) C8(-2.25,0.25) C9(-2.25,0.75) C10(-2.25,1.25) C11(-2.25,1.75) C12(-2.25,2.25) C13(-2.25,2.75) C14(-2.25,3.25) D1(-1.75,-3.25) D2(-1.75,-2.75) D3(-1.75,-2.25) D4(-1.75,-1.75) D12(-1.75,2.25) D13(-1.75,2.75) D14(-1.75,3.25) E1(-1.25,-3.25) E2(-1.25,-2.75) E3(-1.25,-2.25) E5(-1.25,-1.25) E6(-1.25,-0.75) E7(-1.25,-0.25) E8(-1.25,0.25) E9(-1.25,0.75) E10(-1.25,1.25) E12(-1.25,2.25) E13(-1.25,2.75) E14(-1.25,3.25) F1(-0.75,-3.25) F2(-0.75,-2.75) F3(-0.75,-2.25) F5(-0.75,-1.25) F10(-0.75,1.25) F12(-0.75,2.25) F13(-0.75,2.75) F14(-0.75,3.25) G1(-0.25,-3.25) G2(-0.25,-2.75) G3(-0.25,-2.25) G5(-0.25,-1.25) G10(-0.25,1.25) G12(-0.25,2.25) G13(-0.25,2.75) G14(-0.25,3.25) H1(0.25,-3.25) H2(0.25,-2.75) H3(0.25,-2.25) H5(0.25,-1.25) H10(0.25,1.25) H12(0.25,2.25) H13(0.25,2.75) H14(0.25,3.25) J1(0.75,-3.25) J2(0.75,-2.75) J3(0.75,-2.25) J5(0.75,-1.25) J10(0.75,1.25) J12(0.75,2.25) J13(0.75,2.75) J14(0.75,3.25) K1(1.25,-3.25) K2(1.25,-2.75) K3(1.25,-2.25) K5(1.25,-1.25) K6(1.25,-0.75) K7(1.25,-0.25) K8(1.25,0.25) K9(1.25,0.75) K10(1.25,1.25) K12(1.25,2.25) K13(1.25,2.75) K14(1.25,3.25) L1(1.75,-3.25) L2(1.75,-2.75) L3(1.75,-2.25) L12(1.75,2.25) L13(1.75,2.75) L14(1.75,3.25) M1(2.25,-3.25) M2(2.25,-2.75) M3(2.25,-2.25) M4(2.25,-1.75) M5(2.25,-1.25) M6(2.25,-0.75) M7(2.25,-0.25) M8(2.25,0.25) M9(2.25,0.75) M10(2.25,1.25) M11(2.25,1.75) M12(2.25,2.25) M13(2.25,2.75) M14(2.25,3.25) N1(2.75,-3.25) N2(2.75,-2.75) N3(2.75,-2.25) N4(2.75,-1.75) N5(2.75,-1.25) N6(2.75,-0.75) N7(2.75,-0.25) N8(2.75,0.25) N9(2.75,0.75) N10(2.75,1.25) N11(2.75,1.75) N12(2.75,2.25) N13(2.75,2.75) N14(2.75,3.25) P1(3.25,-3.25) P2(3.25,-2.75) P3(3.25,-2.25) P4(3.25,-1.75) P5(3.25,-1.25) P6(3.25,-0.75) P7(3.25,-0.25) P8(3.25,0.25) P9(3.25,0.75) P10(3.25,1.25) P11(3.25,1.75) P12(3.25,2.25) P13(3.25,2.75) P14(3.25,3.25)
  silkscreen extent -6.78,-6.02 6.63,5.87, body extent -6.55,-5.8 6.55,5.8, height 1
ICC_QFN56-EPAD_6P5X6P5_P040 [mm] "MCD-03000"
  rect 0.55x0.21 smd mask+0.05: 1(-3.245,2.6) 14(-3.245,-2.6) 29(3.245,-2.6) 42(3.245,2.6)
  rect 0.7x0.21 smd mask+0.05: 2(-3.17,2.2) 3(-3.17,1.8) 4(-3.17,1.4) 5(-3.17,1) 6(-3.17,0.6) 7(-3.17,0.2) 8(-3.17,-0.2) 9(-3.17,-0.6) 10(-3.17,-1) 11(-3.17,-1.4) 12(-3.17,-1.8) 13(-3.17,-2.2) 30(3.17,-2.2) 31(3.17,-1.8) 32(3.17,-1.4) 33(3.17,-1) 34(3.17,-0.6) 35(3.17,-0.2) 36(3.17,0.2) 37(3.17,0.6) 38(3.17,1) 39(3.17,1.4) 40(3.17,1.8) 41(3.17,2.2)
  rect 0.21x0.55 smd mask+0.05: 15(-2.6,-3.245) 28(2.6,-3.245) 43(2.6,3.245) 56(-2.6,3.245)
  rect 0.21x0.7 smd mask+0.05: 16(-2.2,-3.17) 17(-1.8,-3.17) 18(-1.4,-3.17) 19(-1,-3.17) 20(-0.6,-3.17) 21(-0.2,-3.17) 22(0.2,-3.17) 23(0.6,-3.17) 24(1,-3.17) 25(1.4,-3.17) 26(1.8,-3.17) 27(2.2,-3.17) 44(2.2,3.17) 45(1.8,3.17) 46(1.4,3.17) 47(1,3.17) 48(0.6,3.17) 49(0.2,3.17) 50(-0.2,3.17) 51(-0.6,3.17) 52(-1,3.17) 53(-1.4,3.17) 54(-1.8,3.17) 55(-2.2,3.17)
  rect 4.7x4.7 smd mask+0.05: 57(0,0)
  Top Layer region: -2.495,2.97 -2.495,2.82 -2.555,2.82 -2.705,2.97
  Top Layer region: -2.495,-2.97 -2.495,-2.82 -2.555,-2.82 -2.705,-2.97
  Top Layer region: 2.495,2.97 2.495,2.82 2.555,2.82 2.705,2.97
  Top Layer region: -2.97,-2.495 -2.82,-2.495 -2.82,-2.555 -2.97,-2.705
  Top Layer region: 2.97,-2.495 2.82,-2.495 2.82,-2.555 2.97,-2.705
  Top Layer region: -2.97,2.495 -2.82,2.495 -2.82,2.555 -2.97,2.705
  Top Layer region: 2.495,-2.97 2.495,-2.82 2.555,-2.82 2.705,-2.97
  Top Layer region: 2.97,2.495 2.82,2.495 2.82,2.555 2.97,2.705
  silkscreen extent -3.44,3 -3.01,3.42, body extent -3.25,-3.25 3.25,3.25, height 0.91
ICC_TFBGA200_10X14P5_P080_H1P05_PS0P3 [mm] "MCD-04012"
  round 0.3 smd mask+0.05: A1(-4.4,6.825) A2(-3.6,6.825) A3(-2.8,6.825) A4(-2,6.825) A5(-1.2,6.825) A8(1.2,6.825) A9(2,6.825) A10(2.8,6.825) A11(3.6,6.825) A12(4.4,6.825) AA1(-4.4,-6.175) AA2(-3.6,-6.175) AA3(-2.8,-6.175) AA4(-2,-6.175) AA5(-1.2,-6.175) AA8(1.2,-6.175) AA9(2,-6.175) AA10(2.8,-6.175) AA11(3.6,-6.175) AA12(4.4,-6.175) AB1(-4.4,-6.825) AB2(-3.6,-6.825) AB3(-2.8,-6.825) AB4(-2,-6.825) AB5(-1.2,-6.825) AB8(1.2,-6.825) AB9(2,-6.825) AB10(2.8,-6.825) AB11(3.6,-6.825) AB12(4.4,-6.825) B1(-4.4,6.175) B2(-3.6,6.175) B3(-2.8,6.175) B4(-2,6.175) B5(-1.2,6.175) B8(1.2,6.175) B9(2,6.175) B10(2.8,6.175) B11(3.6,6.175) B12(4.4,6.175) C1(-4.4,5.525) C2(-3.6,5.525) C3(-2.8,5.525) C4(-2,5.525) C5(-1.2,5.525) C8(1.2,5.525) C9(2,5.525) C10(2.8,5.525) C11(3.6,5.525) C12(4.4,5.525) D1(-4.4,4.875) D2(-3.6,4.875) D3(-2.8,4.875) D4(-2,4.875) D5(-1.2,4.875) D8(1.2,4.875) D9(2,4.875) D10(2.8,4.875) D11(3.6,4.875) D12(4.4,4.875) E1(-4.4,4.225) E2(-3.6,4.225) E3(-2.8,4.225) E4(-2,4.225) E5(-1.2,4.225) E8(1.2,4.225) E9(2,4.225) E10(2.8,4.225) E11(3.6,4.225) E12(4.4,4.225) F1(-4.4,3.575) F2(-3.6,3.575) F3(-2.8,3.575) F4(-2,3.575) F5(-1.2,3.575) F8(1.2,3.575) F9(2,3.575) F10(2.8,3.575) F11(3.6,3.575) F12(4.4,3.575) G1(-4.4,2.925) G2(-3.6,2.925) G3(-2.8,2.925) G4(-2,2.925) G5(-1.2,2.925) G8(1.2,2.925) G9(2,2.925) G10(2.8,2.925) G11(3.6,2.925) G12(4.4,2.925) H1(-4.4,2.275) H2(-3.6,2.275) H3(-2.8,2.275) H4(-2,2.275) H5(-1.2,2.275) H8(1.2,2.275) H9(2,2.275) H10(2.8,2.275) H11(3.6,2.275) H12(4.4,2.275) J1(-4.4,1.625) J2(-3.6,1.625) J3(-2.8,1.625) J4(-2,1.625) J5(-1.2,1.625) J8(1.2,1.625) J9(2,1.625) J10(2.8,1.625) J11(3.6,1.625) J12(4.4,1.625) K1(-4.4,0.975) K2(-3.6,0.975) K3(-2.8,0.975) K4(-2,0.975) K5(-1.2,0.975) K8(1.2,0.975) K9(2,0.975) K10(2.8,0.975) K11(3.6,0.975) K12(4.4,0.975) N1(-4.4,-0.975) N2(-3.6,-0.975) N3(-2.8,-0.975) N4(-2,-0.975) N5(-1.2,-0.975) N8(1.2,-0.975) N9(2,-0.975) N10(2.8,-0.975) N11(3.6,-0.975) N12(4.4,-0.975) P1(-4.4,-1.625) P2(-3.6,-1.625) P3(-2.8,-1.625) P4(-2,-1.625) P5(-1.2,-1.625) P8(1.2,-1.625) P9(2,-1.625) P10(2.8,-1.625) P11(3.6,-1.625) P12(4.4,-1.625) R1(-4.4,-2.275) R2(-3.6,-2.275) R3(-2.8,-2.275) R4(-2,-2.275) R5(-1.2,-2.275) R8(1.2,-2.275) R9(2,-2.275) R10(2.8,-2.275) R11(3.6,-2.275) R12(4.4,-2.275) T1(-4.4,-2.925) T2(-3.6,-2.925) T3(-2.8,-2.925) T4(-2,-2.925) T5(-1.2,-2.925) T8(1.2,-2.925) T9(2,-2.925) T10(2.8,-2.925) T11(3.6,-2.925) T12(4.4,-2.925) U1(-4.4,-3.575) U2(-3.6,-3.575) U3(-2.8,-3.575) U4(-2,-3.575) U5(-1.2,-3.575) U8(1.2,-3.575) U9(2,-3.575) U10(2.8,-3.575) U11(3.6,-3.575) U12(4.4,-3.575) V1(-4.4,-4.225) V2(-3.6,-4.225) V3(-2.8,-4.225) V4(-2,-4.225) V5(-1.2,-4.225) V8(1.2,-4.225) V9(2,-4.225) V10(2.8,-4.225) V11(3.6,-4.225) V12(4.4,-4.225) W1(-4.4,-4.875) W2(-3.6,-4.875) W3(-2.8,-4.875) W4(-2,-4.875) W5(-1.2,-4.875) W8(1.2,-4.875) W9(2,-4.875) W10(2.8,-4.875) W11(3.6,-4.875) W12(4.4,-4.875) Y1(-4.4,-5.525) Y2(-3.6,-5.525) Y3(-2.8,-5.525) Y4(-2,-5.525) Y5(-1.2,-5.525) Y8(1.2,-5.525) Y9(2,-5.525) Y10(2.8,-5.525) Y11(3.6,-5.525) Y12(4.4,-5.525)
  silkscreen extent -5.2,-7.3 5.05,7.45, body extent -5.05,-7.3 5.05,7.3, height 1.06
IND_2016_MURATA_LQM2MPN2R2NG0 [mm]
  rect 0.8x1.8 smd mask+0.05: 1(-0.8,0) 2(0.8,0)
  silkscreen extent -0.28,-0.87 0.28,0.87, body extent -1.07,-0.87 1.08,0.87, height 1
IND_2520_TOKO_DFE252012P [mm]
  rect 0.8x2 smd mask+0.05: 1(-1,0) 2(1,0)
  silkscreen extent -1.35,-1.12 1.35,1.12, body extent -1.35,-1.1 1.35,1.1, height 2
LED_0603_OSRAM_LG-Q396-PS-35_GREEN_1A2K_H0P4 [mm]
  rect 0.8x0.8 smd mask+0.05: 1(-0.75,0) 2(0.75,0)
  silkscreen extent -0.85,-0.53 1.28,0.53, body extent -0.85,-0.45 0.85,0.45, height 0.6
LINK200 [mm]
  rect 0.2x0.35 smd paste-10 mask+0.05: 1(0,-0.225) 2(0,0.225)
R0201_H0P23 [mm]
  rect 0.4x0.5 smd mask+0.05: 1(-0.3,0) 2(0.3,0)
  body extent -0.32,-0.17 0.32,0.17, height 0.26
R0402 [mm]
  rect 0.51x0.7 smd mask+0.05: 1(-0.45,0) 2(0.45,0)
  body extent -0.52,-0.3 0.52,0.3, height 0.4
R0603 [mm]
  rect 0.64x1 smd mask+0.05: 1(-0.7,0) 2(0.7,0)
  silkscreen extent -1.05,-0.58 1.05,0.58, body extent -0.9,-0.5 0.9,0.5, height 0.56
SWI_WE_434121025816 [mm] "MCD-03492"
  rect 1.5x1.4 smd: 1(-3.25,0) 2(3.25,0)
  silkscreen extent -3,-1.95 3,1.95, body extent -3.65,-1.95 3.65,1.95, height 2.51
TP_SMD_1MM [mm]
  round 1 smd paste-10 mask+0.05: 1(0,0)
  silkscreen extent -0.7,-0.7 0.7,0.7

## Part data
B2: library part MCD-03492, "Switch tactile, SPST-NO, 50mA, 12V, 6x3.8mm", Manufacturer="WURTH ELEKTRONIC", Manufacturer_Part_Number=434121025816, Package=6x3.8mm
C1 C2 C3 C4 C5 C6 C7 C8 C9 C10 C11 C12 C13 C14 C15 C16 C17 C25 C31 C44 C45 C46 C47 C52 C53 C54 C55 C56 C57 C58 C59 C60 C67: library part MCD-02377, "Capacitor, MLCC, 1uF, 6.3V, X5R, +/-20%, 0201, T=0,3mm", Alternate_Manufacturer=N/A, Manufacturer=MURATA, Manufacturer_Part_Number=GRM033R60J105MEA2, Package=0201
C18 C42: library part MCD-01796, "Capacitor, Tantalum, 100uF, 6V3, 40mR, +/-20%,  Type_B (3528 metric), T=1.9mm", Manufacturer=AVX, Manufacturer_Part_Number=TCJB107M006R0040, Package="3528 (metric)"
C19 C21 C152 C157 C186 C187 C193 C204 C206 C207: library part MCD-03139, "Capacitor, MLCC, 22uF, 10V, X5R, +/-20%, 0805, T=1,25mm", Manufacturer=MURATA, Manufacturer_Part_Number=GRM21BR61A226ME51L, Package=0805
C20 C29 C30 C32 C38 C184 C199: library part MCD-00099, "Capacitor, MLCC, 10uF, 10V, X5R, +/-10%, 0603, T=0,8mm", Alternate_Manufacturer=N/A, Manufacturer=MURATA, Manufacturer_Part_Number=GRM188R61A106KE69D, Package=0603
C22 C23 C24 C26 C27 C28 C34 C35 C36 C37 C41 C183 C200 C202: library part MCD-00100, "Capacitor, MLCC, 22uF, 6V3, X5R, +/-20%, 0603, T=0,8mm", Alternate_Manufacturer=N/A, Manufacturer=MURATA, Manufacturer_Part_Number=GRM188R60J226MEA0J, Package=0603
C33: library part MCD-00011, "Capacitor, MLCC, 10nF, 16V, X7R, 10%, 0402, T=0.5mm", Manufacturer=YAGEO, Manufacturer_Part_Number=CC0402KRX7R7BB103, Package=C0402
C39 C43 C153 C154 C188: library part MCD-00095, "Capacitor, MLCC, 1uF, 25V, X5R, +/-10%, 0402, T=0.5mm", Manufacturer=MURATA, Manufacturer_Part_Number=GRM155R61E105KA12, Package=0402
C40: library part MCD-03140, "Capacitor, MLCC, 10uF, 6.3V, X5R, +/-20%, 0402, T=0.5mm", Manufacturer=MURATA, Manufacturer_Part_Number=GRM155R60J106ME05D, Package=0402
C50 C101 C102 C103 C104 C105 C106 C107 C108 C124 C125 C130 C131 C151 C175 C177 C179 C182: library part MCD-00006, "Capacitor, MLCC, 100nF, 16V, X7R, +/-10%, 0402, T=0.5mm", Alternate_Manufacturer=MURATA, Alternate_Manufacturer_Part_Number=GCM155R71C104KA55D, Manufacturer=YAGEO, Manufacturer_Part_Number=CC0402KRX7R7BB104, Package=0402
C51 C100 C123 C176: library part MCD-01341, "Capacitor, MLCC, 10uF, 6V3, X5R, +/-20%, 0603, T=0,8mm", Alternate_Manufacturer=MURATA, Alternate_Manufacturer_Part_Number=GRM188R60J106ME84D, Manufacturer_Part_Number=GRM188R60J106ME47D, Package=0603
C61: library part MCD-01534, "Capacitor, MLCC, 4,7uF, 6V3, X5R, +/-20%, 0201, T=0.5mm", Alternate_Manufacturer=N/A, Manufacturer=MURATA, Manufacturer_Part_Number=GRM035R60J475ME15, Package=0201
C62 C63 C64 C65 C66 C68 C69 C70 C71 C72 C73 C74 C75 C89 C96 C97 C98 C212 C234 C275 C285: library part MCD-01535, "Capacitor, MLCC,100nF, 10V, X7R, +/-10%, 0201, T=0.3mm", Alternate_Manufacturer=N/A, Manufacturer=MURATA, Manufacturer_Part_Number=GRM033R61A104KE15, Package=0201
C79: library part MCD-02235, "Capacitor, MLCC, 2.2uF, 10V, X5R,+/-10%, 0201, T=0.5mm", Manufacturer=MURATA, Manufacturer_Part_Number=GRM033R61A225KE47D, Package=0201
C81 C86 C90 C92: library part MCD-00674, "Capacitor, MLCC, 6.8pF, 50V, NPO, +-0.25pF, 0402, T=0.5mm", Alternate_Manufacturer=N/A, Manufacturer=YAGEO, Manufacturer_Part_Number=CC0402CRNPO9BN6R8, Package=0402
C87: library part MCD-00006, "Capacitor,100nF,16V,X7R,10%,0402", Alternate_Manufacturer=MURATA, Alternate_Manufacturer_Part_Number=GCM155R71C104KA55D, Manufacturer=YAGEO, Manufacturer_Part_Number=CC0402KRX7R7BB104, Package=0402
C88: library part MCD-01823, "Capacitor, MLCC, 2.2uF, 6V3, X5R,+/-10%, 0402, T=0.5mm", Alternate_Manufacturer=N/A, Manufacturer=MURATA, Manufacturer_Part_Number=GRM155R60J225KE95D, Package=0402
C91 C141 C142 C156 C189 C190 C208 C209 C217: library part MCD-01356, "Capacitor, MLCC, 4.7uF, 6V3, X5R, +/-20%, 0402, T=0.5mm", Manufacturer=MURATA, Manufacturer_Part_Number=GRM155R60J475ME47, Package=0402
C155: library part MCD-02198, "Capacitor, MLCC, 10nF, 50V, X7R, +/-10%, 0402, T=0.5mm", Manufacturer=YAGEO, Manufacturer_Part_Number=CC0402KRX7R9BB103, Package=0402
C178 C180 C181: library part MCD-02606, "Capacitor, MLCC, 2.2uF, 6.3V, X5R, +/-10%, 0402, T=0.5mm", Manufacturer=YAGEO, Manufacturer_Part_Number=CC0402KRX5R5BB225, Package=0402
CN12: library part MCD-00655, "Header 2 circuits, 1.25mm Pitch ,  Vertical, with Friction Lock", Alternate_Manufacturer=N/A, Manufacturer=MOLEX, Manufacturer_Part_Number=53047-0210
D5: library part MCD-00034, Manufacturer=STMICROELECTRONICS, Manufacturer_HQ_COO=EU
D6: library part MCD-03280, "Diode, Schottky, Dual Common Cathode, 0V3, 300mA, 40V, SOT-23", Manufacturer=STMICROELECTRONICS, Manufacturer_Part_Number=BAT54CFILM, Package=SOT-23
L1 L6: library part MCD-03143, "Inductor, 2.2uH, +/-20%, Itemp= 1700mA, Isat= 2400mA, 0R140, 0806, T=1mm", Manufacturer=MURATA, Manufacturer_Part_Number=DFE201610E-2R2M{}P2, Package=0806
L2 L4: library part MCD-03142, "Inductor, 0.68uH, +/-20%, Itemp= 3900mA, Isat= 5400mA, 0R031, 1008, T=1.2mm", Manufacturer=MURATA, Manufacturer_Part_Number=DFE252012F-R68M{}P2, Package=1008
L3 L5 L7: library part MCD-03141, "Inductor, 0.68uH, +/-20%, Itemp= 3100mA, Isat= 4300mA, 0R043, 0806, T=1mm", Manufacturer=MURATA, Manufacturer_Part_Number=DFE201610E-R68M{}P2, Package=0806
LD11: library part MCD-00588, "LED Green, 0603 SMD, Forward Voltage Typ=2V, Max=2.5V", Alternate_Manufacturer="VISHAY SEMICONDUCTOR OPTO DIVISION", Alternate_Manufacturer_Part_Number=VLMTG1300-GS08, Manufacturer="OSRAM OPTO SEMICONDUCTORS", Manufacturer_Part_Number="LG Q396-PS-35", Package="LED 0603"
LNK1 LNK2 LNK4 LNK7 LNK8 LNK11: library part MCD-02777, "Track link on PCB 200um width for layout routing", Manufacturer=N/A
R1 R163: library part MCD-02253, "Resistor, 240R, 0201, +/-1%, 1/20W", Alternate_Manufacturer=N/A, Manufacturer=YAGEO, Manufacturer_Part_Number=RC0201FR-07240RL, Package=0201
R2 R46 R57 R59 R60 R64 R75 R81 R267 R269 R286: library part MCD-00052, "Resistor,0R,0402,5%,1/16W", Alternate_Manufacturer=N/A, Manufacturer=YAGEO, Manufacturer_Part_Number=RC0402JR-070RL, Package=0402
R27 R272: library part MCD-00053, "Resistor,10K,0402,1%,1/16W", Alternate_Manufacturer=N/A, Manufacturer=YAGEO, Manufacturer_Part_Number=RC0402FR-0710KL, Package=0402
R37 R44 R49 R248: library part MCD-00053, "Resistor,10K,0402,1%,1/16W", Manufacturer=YAGEO, Manufacturer_Part_Number=RC0402FR-0710KL, Package=0402
R66: library part MCD-00058, "Resistor, 20R, 0402, +/-1%, 1/16W", Alternate_Manufacturer=N/A, Manufacturer=YAGEO, Manufacturer_Part_Number=RC0402FR-0720RL, Package=0402
R67: library part MCD-00052, "Resistor, 0R, 0402, +/-5%, 1/16W", Manufacturer=YAGEO, Manufacturer_Part_Number=RC0402JR-070RL, Package=0402
R156: library part MCD-00053, "Resistor, 10K, 0402, +/-1%, 1/16W", Alternate_Manufacturer=N/A, Manufacturer=YAGEO, Manufacturer_Part_Number=RC0402FR-0710KL, Package=0402
R210: library part MCD-00441, "Resistor,270R,0402,1%,1/16W", Manufacturer=YAGEO, Manufacturer_Part_Number=RC0402FR-07270RL, Package=0402
R249: library part MCD-00056, "Resistor, 0R, 0603, +/-5%, 1/10W", Manufacturer=YAGEO, Manufacturer_Part_Number=RC0603JR-070RL, Package=0603
R260 R261: library part MCD-00068, "Resistor,1K5,0402,1%,1/16W", Manufacturer=YAGEO, Manufacturer_Part_Number=RC0402FR-071K5L, Package=0402
TP9: library part MCD-00074, "Test Point 1mm", Manufacturer=n/a
U2: library part MCD-04160, "Memory, LPDDR4 SDRAM,1V8, 32Gbit, 2133MHz", Manufacturer=MICRON, Package=TFBGA-200
U24: library part MCD-02799, "Memory, eMMC, 4GB, 15nm ,WFBGA , 153 pins", Manufacturer=KIOXIA, Manufacturer_Part_Number=THGBMTG5D1LBAIL, Package=WFBGA153
U26: library part MCD-03000, "STPMIC2", Manufacturer=STMICROELECTRONICS, Package=VQFN
U27: library part MCD-02000, "MPU, ARM Cortex-A35 + M33 32-bit MPU, 808KB RAM, With Crypto", Manufacturer=STMICROELECTRONICS, Manufacturer_HQ_COO=EU, Package=LFBGA-436
X1: library part MCD-01479, "Crystal, 32.768kHz, 6pF, +/-20ppm, 80K, 2.05x1.2mm", Manufacturer=NDK, Manufacturer_Part_Number=NX2012SA-32.768KHZ-EXS00A-MU00527, Package=2.05x1.2mm
X2: library part MCD-02344, "Crystal, 40MHz, 6pF, +/-20ppm, 80R, 1.6x1.2mm", Manufacturer=NDK, Manufacturer_Part_Number=NX1612SA-40MHZ-EXS00A-CS13836, Package=1.6x1.2mm

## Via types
v1: diameter 0.55, hole 0.35, Top Layer to Bottom Layer, 387 vias
v2: diameter 0.4, hole 0.2, Top Layer to Bottom Layer, tented both sides, 173 vias
v3: diameter 0.5, hole 0.2, Top Layer to Bottom Layer, 146 vias
v4: diameter 0.4, hole 0.2, Top Layer to Bottom Layer, 129 vias
v5: diameter 0.5, hole 0.25, Top Layer to Bottom Layer, 3 vias

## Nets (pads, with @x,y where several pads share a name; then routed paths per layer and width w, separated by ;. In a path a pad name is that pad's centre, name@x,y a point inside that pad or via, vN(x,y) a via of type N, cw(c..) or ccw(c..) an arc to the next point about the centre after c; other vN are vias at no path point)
1V8: C72.2 C89.2 C96.2 C97.2 C98.2 C152.2 C157.2 C178.2 C179.2 C193.2 C212.2 C275.2 C285.2 L1.2 LNK1.2 R37.2 R44.2 R49.2 R248.2 R267.2 R269.1 U24.C6 U24.M4 U24.N4 U24.P3 U24.P5 U27.C4 U27.C7 U27.F6 U27.F10 U27.G17 U27.J16 U27.K8 U27.L8 U27.U17 U27.W18 | length 114.1
  Top Layer w0.15: U24.P3@112.48,91.042 v2(112.88,91.042)
  Top Layer w0.2: LNK1.2@60.6,84.348 v1(60.6,84.95) ; v2(87.6,79.6) U27.C4@88,79.2 v2(87.6,79.6) ; v2(89.2,77.2) U27.F6@89.6,76.8 ; U27.C7@90.4,79.2 90.415,79.185 90.415,79.02 v2(90.66,78.775) ; U27.L8@91.2,72.8 91.175,72.8 v2(90.8,73.175) 91.2,73.575 U27.K8@91.2,73.6 ; v2(91.624,77.173) 92.413,77.173 92.786,76.8 U27.F10@92.8,76.8 ; U27.J16@97.6,74.4 98,74.8 v2(98,76.375) 98.012,76.375 98.388,76 U27.G17@98.4,76 ; U27.U17@98.4,68 v2(98.8,67.6) ; v2(98.868,66.067) U27.W18@99.2,66.4 ; U24.C6@106.98,92.542 107.157,92.719 107.432,92.719 v1(107.48,92.767) ; U24.M4@111.48,91.542 U24.N4@111.98,91.542 ; U24.P3@112.48,91.042 U24.N4@111.98,91.542 ; U24.P5@112.48,92.042 U24.N4@111.98,91.542
  Top Layer w0.64: C152.2@59.5,84.95 v1(60.6,84.95) v1(61.28,84.95) 61.142,85.088 v1(61.142,94.8)
  Top Layer w0.8: L1.2@57.495,83.175 57.495,84.9 57.545,84.95 C157.2@57.65,84.95
  Top Layer w0.9: C193.2@55.8,84.95 C157.2@57.545,84.95 ; C157.2@57.65,84.95 C152.2@59.5,84.95
  Signal Layer 2 w0.2: 96.075,70.9 95.825,71.15 95.484,71.15 95.399,71.235 95.248,71.386 95.248,72.063 95.201,72.109 95.201,73.292 95.317,73.408 95.317,73.433 95.434,73.55 95.723,73.55 96.007,73.834 96.007,74.166 96.003,74.169 96.257,74.423 96.684,74.423 ; v2(98.868,66.067) v2@98.868,66.094
  Signal Layer 2 w0.3: v1(86.019,84.939) 92.721,84.939 97.371,80.289 97.371,77.004 v2(98,76.375) ; 96.075,70.9 96.075,69.048 96.075,69.014 96.339,68.75 97.65,68.75 v2(98.8,67.6) ; 96.684,74.423 97.65,75.389 97.65,76.018 v2@98,76.367 ; v2(98.8,67.6) 99.15,67.25 99.15,66.377 v2@98.868,66.094
  Signal Layer 2 w0.64: v1@60.6,84.955 v1@61.28,84.955 ; v1(61.28,84.95) 86.009,84.95 v1(86.019,84.939)
  Bottom Layer w0.17: C89.2@97.35,67.825 97.415,67.89 97.44,67.89 97.56,68.01 98.39,68.01 v2(98.8,67.6)
  Bottom Layer w0.2: R269.1@85.854,69.315 85.854,69.41 86.009,69.565 86.104,69.565 86.35,69.811 R267.2@86.35,70.375 ; R267.2@86.325,70.715 86.697,71.087 89.377,71.087 89.723,71.434 89.723,72.448 90.059,72.783 90.457,72.783 90.8,73.127 v2(90.8,73.175) ; v2(89.2,77.2) 89.458,76.942 89.458,75.927 89.985,75.4 89.985,73.99 v2(90.8,73.175) ; v2(90.66,78.775) 90.66,78.79 90.825,78.955 C97.2@90.825,79.375 ; C212.2@91.31,73.1 91.272,73.138 90.837,73.138 v2(90.8,73.175) ; C96.2@98.85,65.55 98.85,66.05 v2(98.868,66.067) ; R44.2@105.95,91.65 106,91.65 106.155,91.805 106.155,92.075 106.655,92.575 106.655,92.6 106.81,92.755 C178.2@106.835,92.755 ; R37.2@111.775,90.27 111.777,90.272 112.308,90.272 112.458,90.422 112.458,90.87 112.634,91.046 ; R49.2@111.775,92.85 111.792,92.833 112.342,92.833 ; 112.648,92.008 112.648,92.527 112.342,92.833 ; R248.2@112.682,93.854 112.527,93.699 112.527,93.49 112.525,93.488 112.525,93.016 112.342,92.833
  Bottom Layer w0.3: C98.2@87.175,79.175 v2(87.6,79.6) ; C72.2@91.6,77.7 91.6,77.224 91.624,77.2 v2(91.624,77.173) ; C285.2@97.555,74.91 97.94,75.295 97.94,76.288 98,76.348 v2(98,76.375) ; C178.2@106.835,92.755 v1@107.5,92.755 ; 112.634,91.994 112.43,91.79 112.43,91.356 112.634,91.152 112.634,91.046 v2@112.876,91.046 ; 112.648,92.008 112.667,92.027 C179.2@113.586,92.027
  Bottom Layer w0.4: C275.2@88.675,77.2 v2(89.2,77.2)
  other v1: 85.224,84.95 61.131,94.047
